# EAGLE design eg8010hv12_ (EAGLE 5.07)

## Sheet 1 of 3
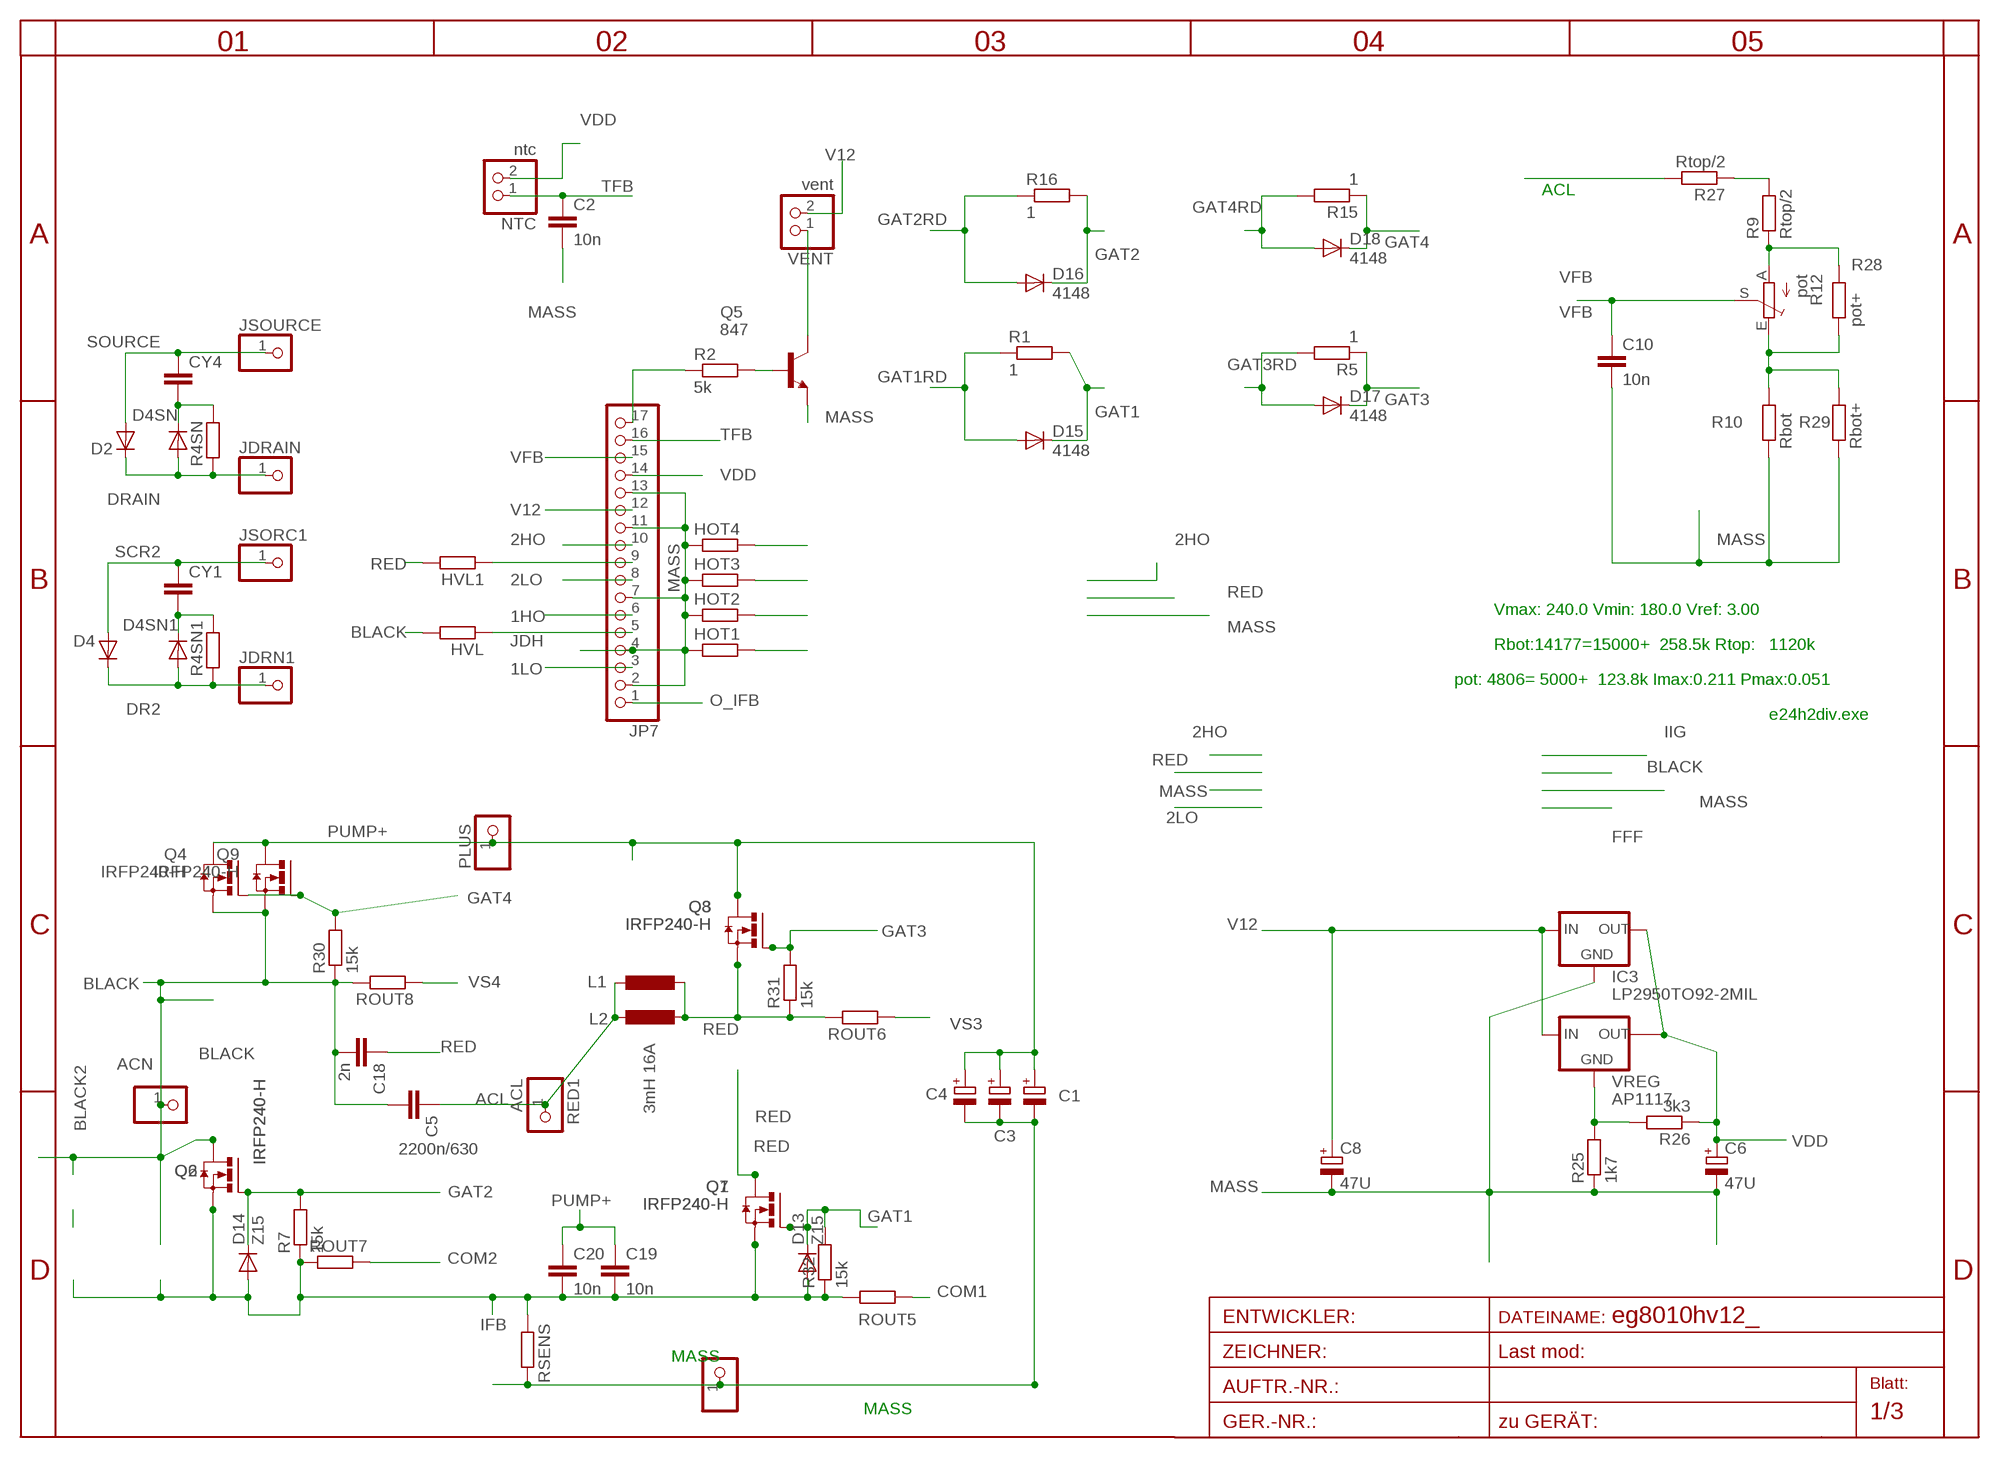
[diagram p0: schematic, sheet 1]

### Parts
BLACK2  ACN  PINHD-1X12MM3  [1X2MM3]
C1  CPOL-EUE5-13  [E5-13]
C2  10n  C-EUC0805  [C0805]
C3  CPOL-EUE5-13  [E5-13]
C4  CPOL-EUE5-13  [E5-13]
C5  2200n/630  C-EU275-173X316  [C275-173X316]
C6  47U  CPOL-EUSMCA  [SMC_A]
C8  47U  CPOL-EUSMCA  [SMC_A]
C10  10n  C-EUC0805  [C0805]
C18  2n  C-EU050-024X044  [C050-024X044]
C19  10n  C-EU050-024X044  [C050-024X044]
C20  10n  C-EU050-024X044  [C050-024X044]
CY1  CXXC10B5  [XC10B5]
CY4  CXXC10B5  [XC10B5]
D2  DIODE-SMC  [SMC]
D4  DIODE-SMC  [SMC]
D4SN  DIODE-P1-10  [P1-10]
D4SN1  DIODE-P1-10  [P1-10]
D13  Z15  DIODE-MINIMELF  [MINIMELF]
D14  Z15  DIODE-MINIMELF  [MINIMELF]
D15  4148  DIODE-MINIMELF  [MINIMELF]
D16  4148  DIODE-MINIMELF  [MINIMELF]
D17  4148  DIODE-MINIMELF  [MINIMELF]
D18  4148  DIODE-MINIMELF  [MINIMELF]
HOT1  R-EU_R0805  [R0805]
HOT2  R-EU_R0805  [R0805]
HOT3  R-EU_R0805  [R0805]
HOT4  R-EU_R0805  [R0805]
HVL  R-EU_R1005  [R1005]
HVL1  R-EU_R1005  [R1005]
IC3  LP2950TO92-2MIL  [TO92-2MIL]
JDRAIN  PINHD-1X11MM0  [1X1MM0]
JDRN1  PINHD-1X11MM0  [1X1MM0]
JP7  PINHD-1X17  [1X17]
JSORC1  PINHD-1X11MM0  [1X1MM0]
JSOURCE  PINHD-1X11MM0  [1X1MM0]
L1  L-EU4.13  [0204/13]
L2  3mH 16A  L-EURNG  [RING]
MINUS  PINHD-1X12MM3  [1X2MM3]
NTC  ntc  PINHD-1X2STR  [1X02]
PLUS  PINHD-1X12MM3  [1X2MM3]
Q1  IRFP240-H  [TO247BH]
Q2  IRFP240-H  [TO247BH]
Q3  IRFP240-H  [TO247BH]
Q4  IRFP240-H  [TO247BH]
Q5  847  BC847SMD  [SOT23]
Q6  IRFP240-H  [TO247BH]
Q7  IRFP240-H  [TO247BH]
Q8  IRFP240-H  [TO247BH]
Q9  IRFP240-H  [TO247BH]
R1  1  R-EU_R2512  [R2512]
R2  5k  R-EU_R0805  [R0805]
R4SN  R-EU_0207/10  [0207/10]
R4SN1  R-EU_0207/10  [0207/10]
R5  1  R-EU_R2512  [R2512]
R7  15k  R-EU_R1206  [R1206]
R9  Rtop/2  R-EU_R1206  [R1206]
R10  Rbot  R-EU_R0805  [R0805]
R12  pot  TRIM_EU-B64Y  [B64Y]
R15  1  R-EU_R2512  [R2512]
R16  1  R-EU_R2512  [R2512]
R25  1k7  R-EU_R0805  [R0805]
R26  3k3  R-EU_R0805  [R0805]
R27  Rtop/2  R-EU_R1206  [R1206]
R28  pot+  R-EU_R0805  [R0805]
R29  Rbot+  R-EU_R0805  [R0805]
R30  15k  R-EU_R1206  [R1206]
R31  15k  R-EU_R1206  [R1206]
R32  15k  R-EU_R1206  [R1206]
RED1  ACL  PINHD-1X12MM3  [1X2MM3]
ROUT5  R-EU_R2512  [R2512]
ROUT6  R-EU_R2512  [R2512]
ROUT7  R-EU_R2512  [R2512]
ROUT8  R-EU_R2512  [R2512]
RSENS  R-EU_WIRE  [WIRE]
VENT  vent  PINHD-1X2STR  [1X02]
VREG  AP1117  [SOT223]

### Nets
1HO: HOT2.2 JP7.6 ; also sheet 3
1LO: HOT1.2 JP7.3 ; also sheet 3
2HO: HOT4.2 JP7.10 ; also sheet 3
2LO: HOT3.2 JP7.8 ; also sheet 3
ACL: C5.1 L1.1 L2.2 R27.2 RED1.1
BLACK: BLACK2.1 C5.2 C18.2 HVL.2 Q2.D Q4.S Q6.D Q9.S R30.1 ROUT8.2
COM1: ROUT5.1 ; also sheet 3
COM2: ROUT7.2 ; also sheet 3
DFG: HVL1.1 JP7.9
DR2: D4.C D4SN1.A JDRN1.1 R4SN1.1
DRAIN: D2.C D4SN.A JDRAIN.1 R4SN.1
GAT1: D13.C D15.C Q1.G Q7.G R1.2 R32.2
GAT1RD: D15.A R1.1 ; also sheet 3
GAT2: D14.C D16.C Q2.G Q6.G R7.2 R16.2
GAT2RD: D16.A R16.1 ; also sheet 3
GAT3: D17.C Q3.G Q8.G R5.1 R31.2
GAT3RD: D17.A R5.2 ; also sheet 3
GAT4: D18.C Q4.G Q9.G R15.1 R30.2
GAT4RD: D18.A R15.2 ; also sheet 3
IFB: C19.2 C20.2 D13.A D14.A Q1.S Q2.S Q6.S Q7.S R7.1 R32.1 ROUT5.2 ROUT7.1 RSENS.1 ; also sheet 2,3
JDH: HVL.1 JP7.5
MASS: C1.- C2.2 C3.- C4.- C6.- C8.- C10.2 HOT1.1 HOT2.1 HOT3.1 HOT4.1 IC3.2(GND) JP7.2 JP7.4 JP7.7 JP7.11 JP7.13 MINUS.1 Q5.2(E) R10.1 R25.1 R29.1 RSENS.2 ; also sheet 2,3
N$1: Q5.3(C) VENT.1
N$2: Q5.1(B) R2.2
N$3: JP7.17 R2.1
N$17: R25.2 R26.2 VREG.1(GND)
N$23: R9.2 R27.1
N$29: R10.2 R12.E R28.1 R29.2
N$30: R9.1 R12.A R28.2
O_IFB: JP7.1 ; also sheet 3
PUMP+: C1.+ C3.+ C4.+ C19.1 C20.1 PLUS.1 Q3.D Q4.D Q8.D Q9.D ; also sheet 2
RED: C18.1 HVL1.2 L1.2 L2.1 Q1.D Q3.S Q7.D Q8.S R31.1 ROUT6.2
SCR2: CY1.1 D4.A JSORC1.1
SNUB1: CY1.2 D4SN1.C R4SN1.2
SNUB2: CY4.2 D4SN.C R4SN.2
SOURCE: CY4.1 D2.A JSOURCE.1
TFB: C2.1 JP7.16 NTC.1 ; also sheet 2
V12: C8.+ IC3.3(IN) JP7.12 VENT.2 VREG.3(IN) ; also sheet 2,3
VDD: C6.+ IC3.1(OUT) JP7.14 NTC.2 R26.1 VREG.4(TAB) ; also sheet 2,3
VFB: C10.1 JP7.15 R12.S ; also sheet 2
VS3: ROUT6.1 ; also sheet 3
VS4: ROUT8.1 ; also sheet 3
Unconnected: VREG.2(OUT)

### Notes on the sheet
- Vmax: 240.0 Vmin: 180.0 Vref: 3.00
- Rbot:14177=15000+  258.5k Rtop:   1120k
- pot: 4806= 5000+  123.8k Imax:0.211 Pmax:0.051
- e24h2div.exe

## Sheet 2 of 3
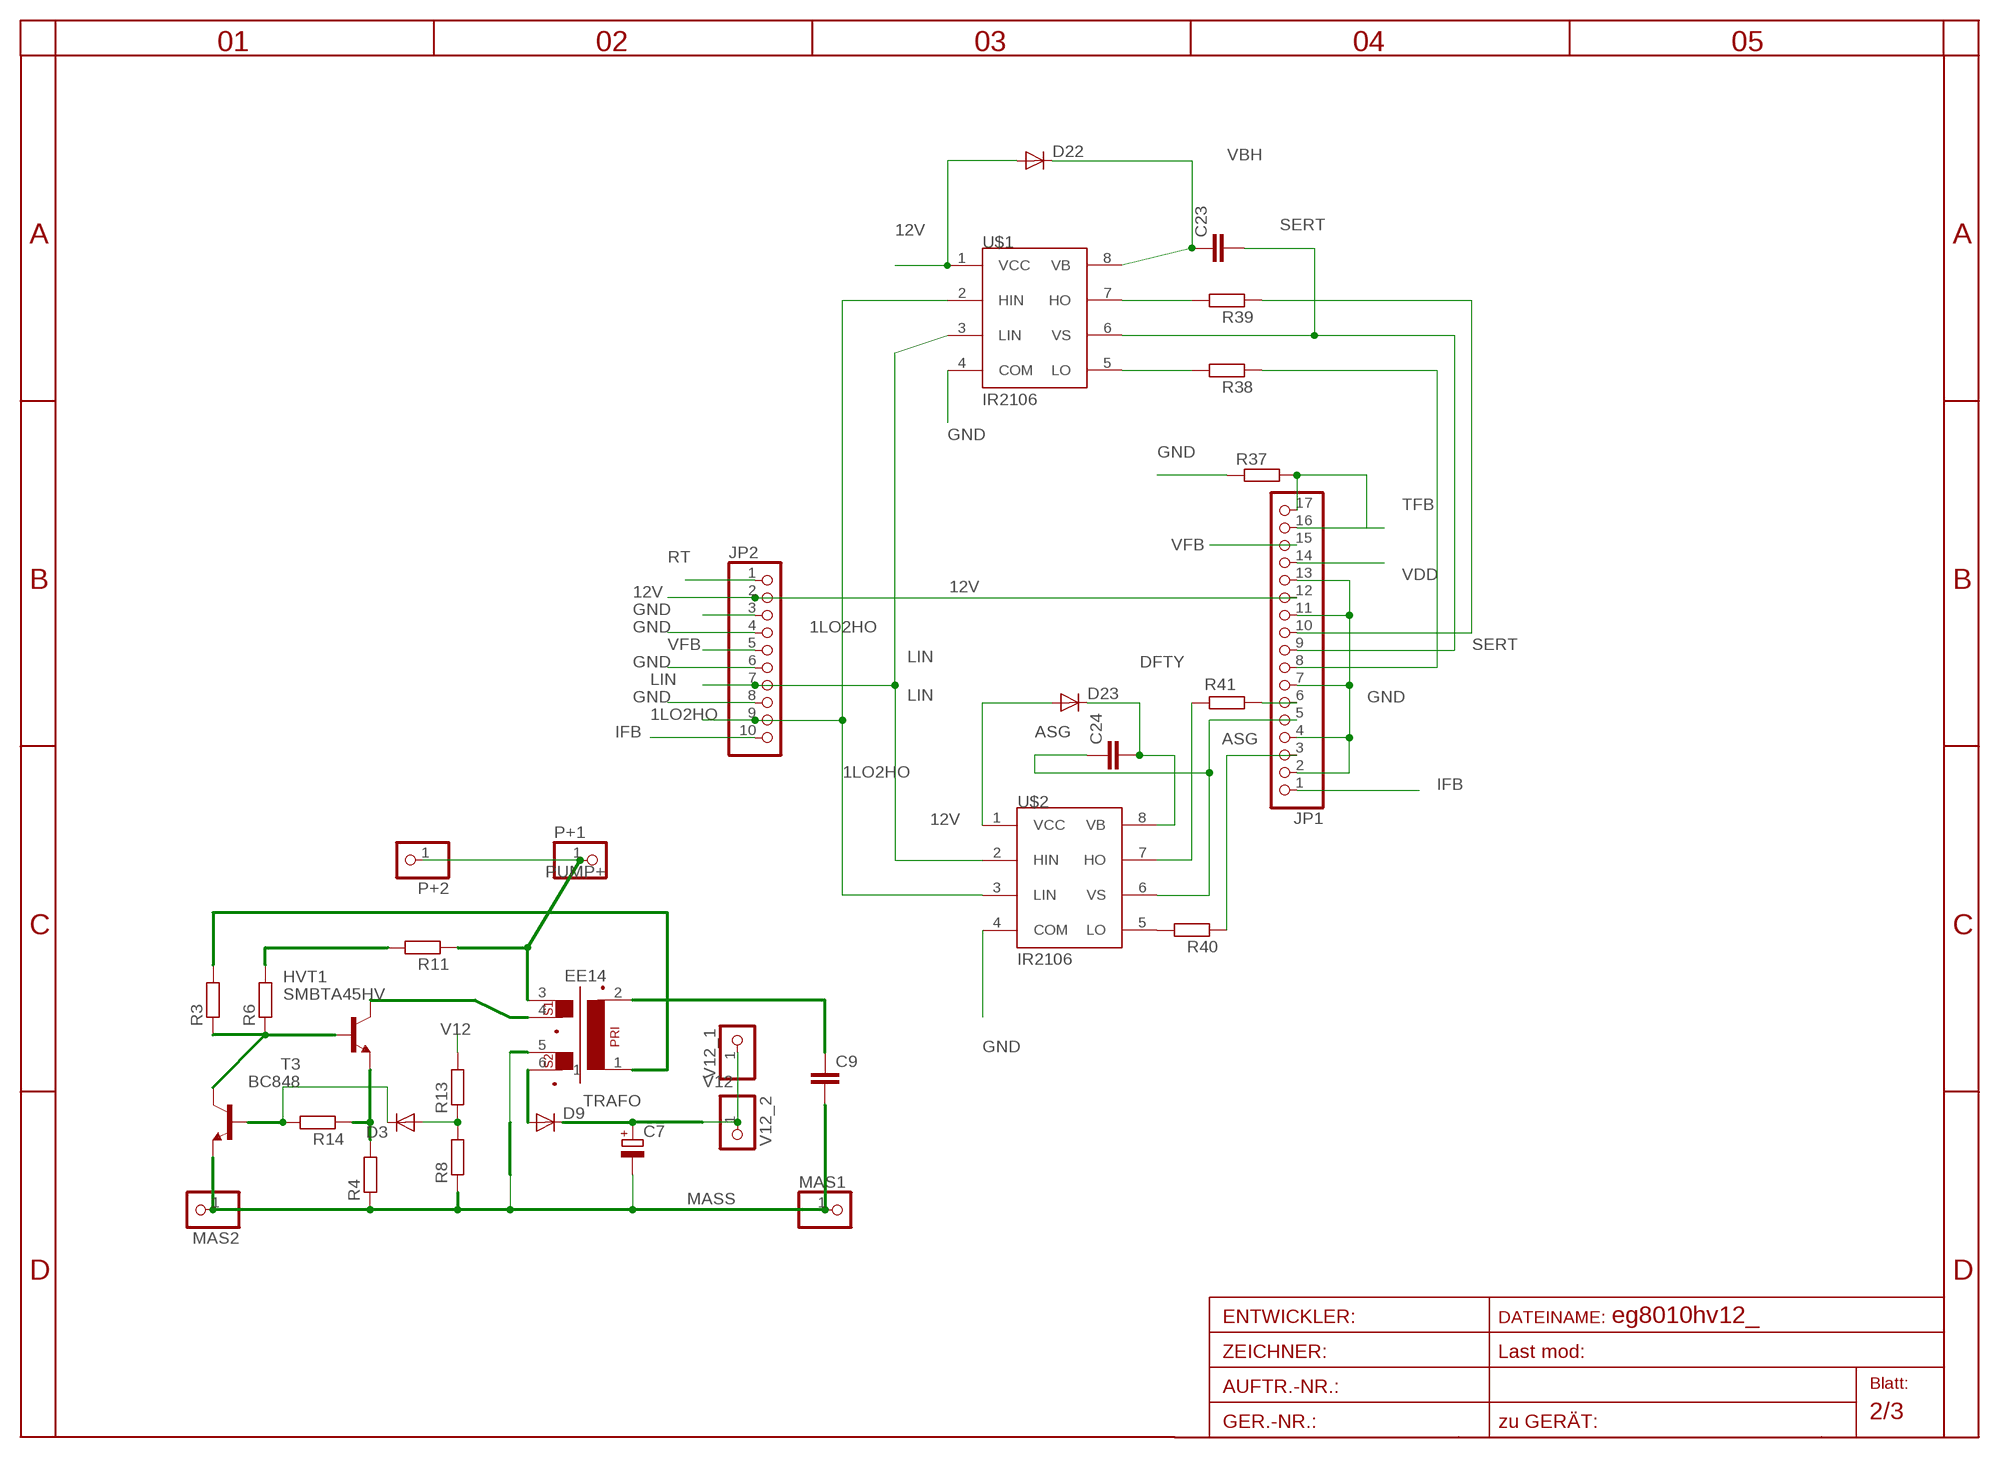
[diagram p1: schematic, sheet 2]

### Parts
C7  CPOL-EUSMCA  [SMC_A]
C9  C-EUC0805  [C0805]
C23  C-EUC1206  [C1206]
C24  C-EUC1206  [C1206]
D3  DIODE-MINIMELF  [MINIMELF]
D9  DIODE-SMA-DO214  [SMA-DO214AC]
D22  DIODE-SMA-DO214  [SMA-DO214AC]
D23  DIODE-SMA-DO214  [SMA-DO214AC]
HVT1  SMBTA45HV  [SOT23HV]
JP1  PINHD-1X17  [1X17]
JP2  PINHD-1X100X05  [1X10]
MAS1  PINHD-1X11X0.4  [1X01]
MAS2  PINHD-1X11X0.4  [1X01]
P+1  PINHD-1X11X0.4  [1X01]
P+2  PINHD-1X11X0.4  [1X01]
R3  R-EU_R0805  [R0805]
R4  R-EU_R0805  [R0805]
R6  R-EU_R1206  [R1206]
R8  R-EU_R0805  [R0805]
R11  R-EU_R1206  [R1206]
R13  R-EU_R0805  [R0805]
R14  R-EU_R0805  [R0805]
R37  R-EU_0204/2V  [0204V]
R38  R-EU_R1206  [R1206]
R39  R-EU_R1206  [R1206]
R40  R-EU_R1206  [R1206]
R41  R-EU_R1206  [R1206]
T3  BC848  [SOT23]
TRAFO  EE14  [EE14]
U$1  IR2106  [SO8-5]
U$2  IR2106  [SO8-5]
V12_1  PINHD-1X11X0.4  [1X01]
V12_2  PINHD-1X11X0.4  [1X01]

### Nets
1LO2HO: JP2.9 U$1.2(HIN) U$2.3(LIN)
12V: D22.A D23.A JP1.12 JP2.2 U$1.1(VCC) U$2.1(VCC)
A: D9.A TRAFO.6
ASG: C24.1 JP1.5 U$2.6(VS)
B1C2: HVT1.1(B) R3.1 R6.1 T3.C
BT1: D3.C R14.2 T3.B
C1: HVT1.3(C) TRAFO.4
DFTY: C24.2 D23.K(C) U$2.8(VB)
EB: HVT1.2(E) R4.2 R14.1
GND: JP1.2 JP1.4 JP1.7 JP1.11 JP1.13 JP2.3 JP2.4 JP2.6 JP2.8 R37.1 U$1.4(COM) U$2.4(COM)
IFB: JP1.1 JP2.10 ; also sheet 1,3
LIN: JP2.7 U$1.3(LIN) U$2.2(HIN)
MASS: C7.- C9.2 MAS1.1 MAS2.1 R4.1 R8.1 T3.E TRAFO.5 ; also sheet 1,3
N$6: R3.2 TRAFO.1
N$7: C9.1 TRAFO.2
N$8: R6.2 R11.2
N$10: D3.A R8.2 R13.1
N$15: JP1.3 R40.1
N$19: R41.2 U$2.7(HO)
N$21: JP1.8 R38.1
N$27: JP1.10 R39.1
N$32: R38.2 U$1.5(LO)
N$33: R39.2 U$1.7(HO)
N$34: JP1.6 R41.1
N$35: R40.2 U$2.5(LO)
PUMP+: P+1.1 P+2.1 R11.1 TRAFO.3 ; also sheet 1
RT: JP2.1
SERT: C23.2 JP1.9 U$1.6(VS)
TFB: JP1.16 JP1.17 R37.2 ; also sheet 1
V12: C7.+ D9.K(C) R13.2 V12_1.1 V12_2.1 ; also sheet 1,3
VBH: C23.1 D22.K(C) U$1.8(VB)
VDD: JP1.14 ; also sheet 1,3
VFB: JP1.15 JP2.5 ; also sheet 1

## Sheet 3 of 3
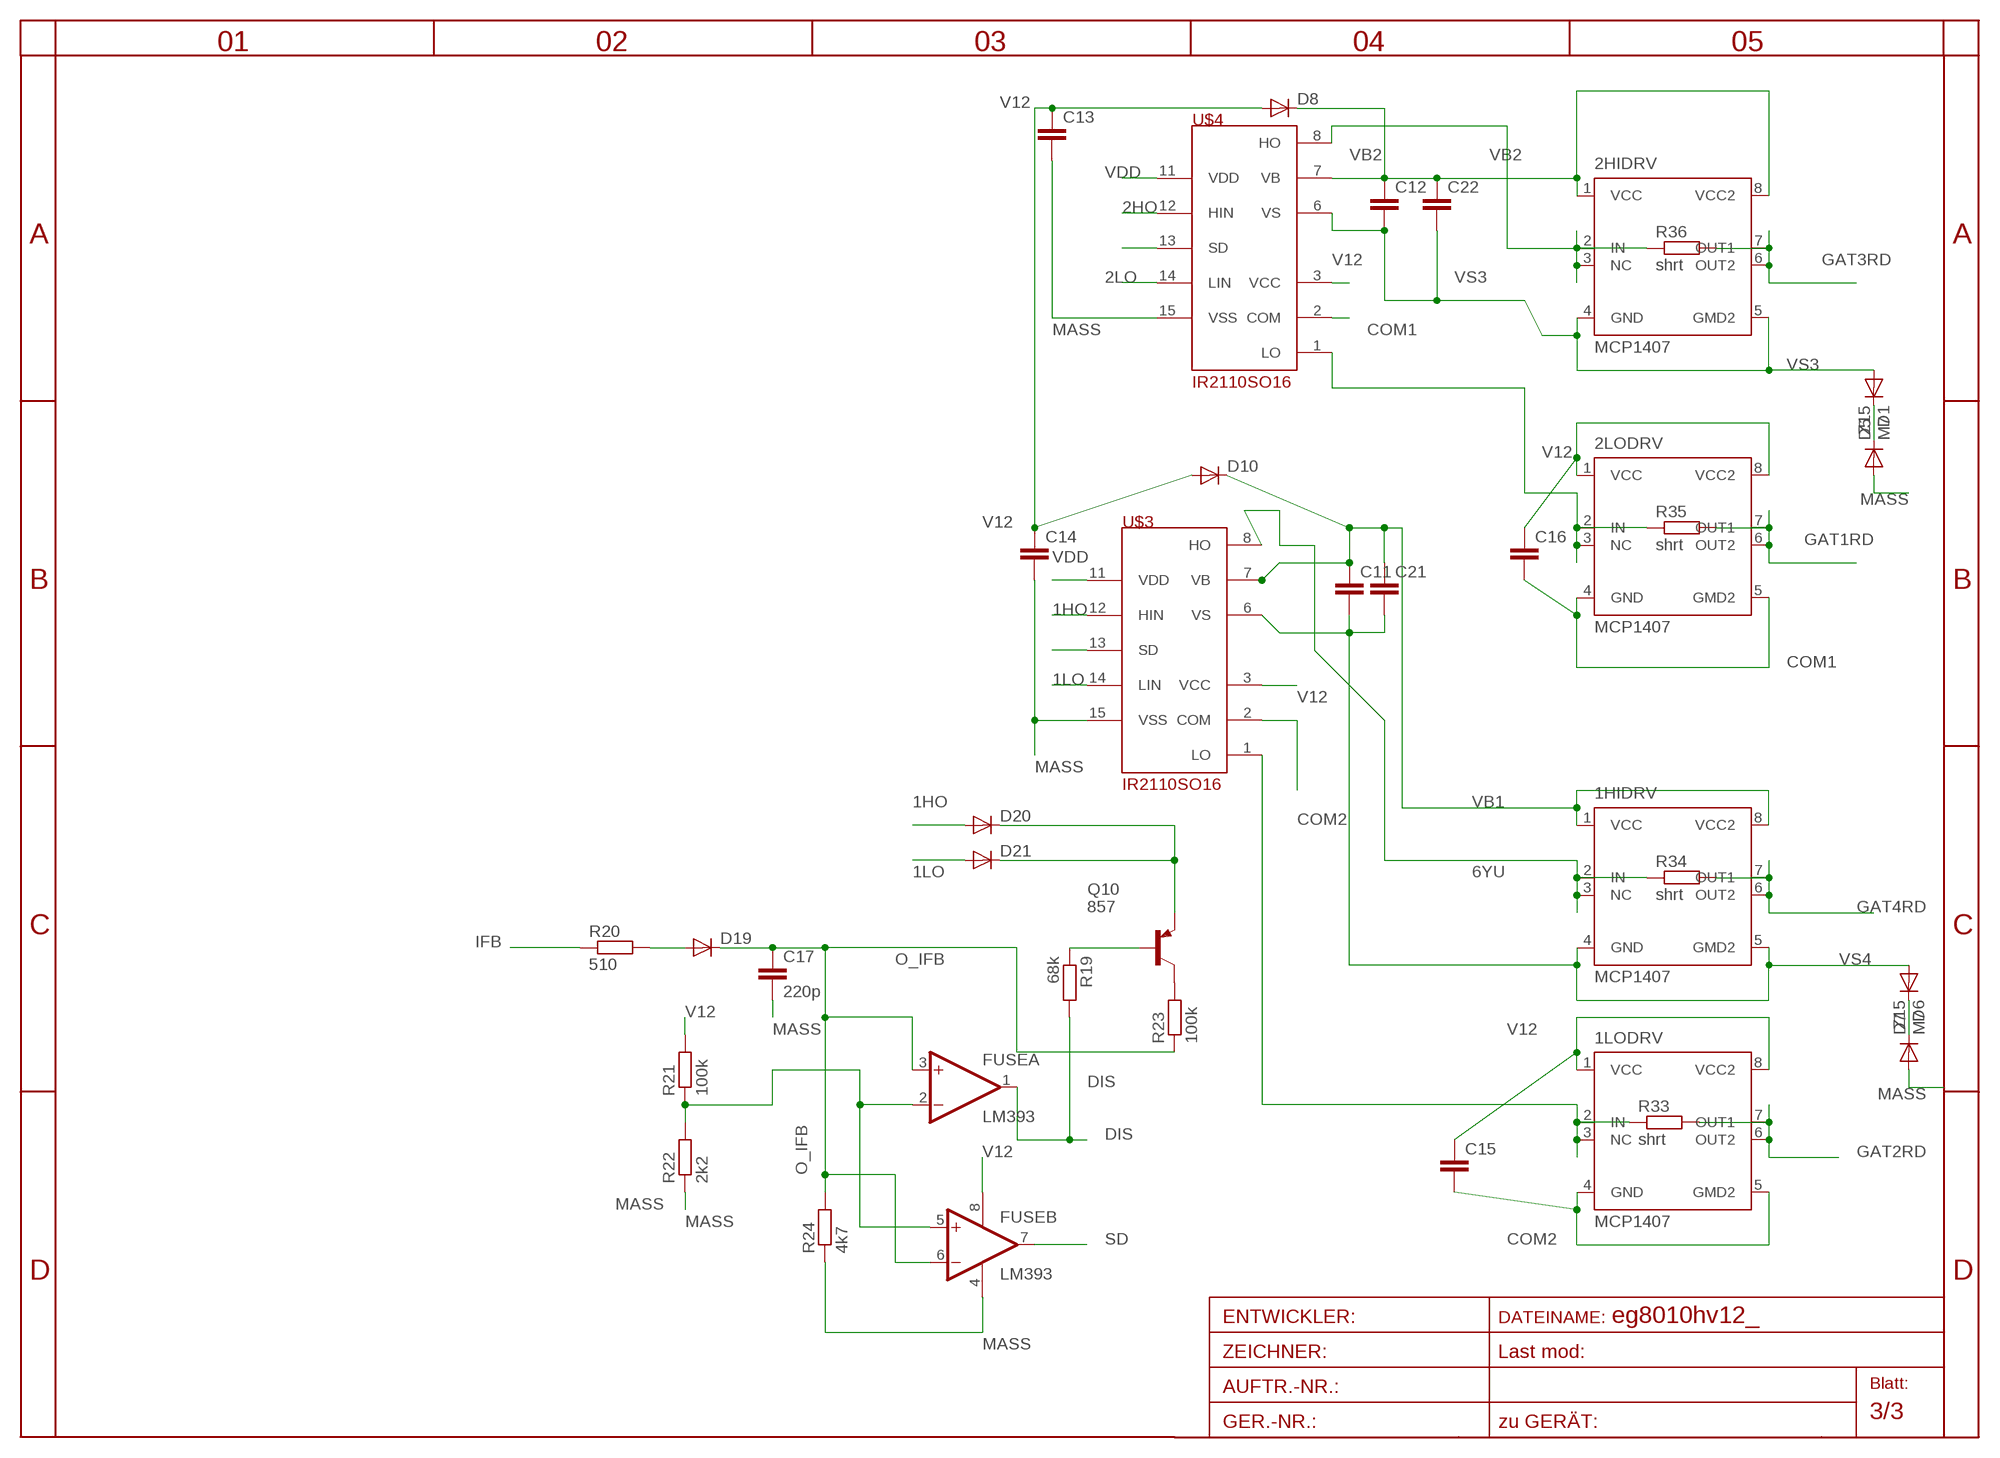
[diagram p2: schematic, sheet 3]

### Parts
1HIDRV  MCP1407  [SO-08M]
1LODRV  MCP1407  [SO-08M]
2HIDRV  MCP1407  [SO-08M]
2LODRV  MCP1407  [SO-08M]
C11  C-EUC058MLCC  [C058-020X040]
C12  C-EUC058MLCC  [C058-020X040]
C13  C-EUC1206  [C1206]
C14  C-EUC1206  [C1206]
C15  C-EUC1206  [C1206]
C16  C-EUC1206  [C1206]
C17  220p  C-EUC0805  [C0805]
C21  C-EUC1206  [C1206]
C22  C-EUC1206  [C1206]
D1  Z15  DIODE-MINIMELF  [MINIMELF]
D5  M7  DIODE-SMA-DO214  [SMA-DO214AC]
D6  Z15  DIODE-MINIMELF  [MINIMELF]
D7  M7  DIODE-SMA-DO214  [SMA-DO214AC]
D8  DIODE-SMA-DO214  [SMA-DO214AC]
D10  DIODE-SMA-DO214  [SMA-DO214AC]
D19  DIODE-SOT23  [SOT23]
D20  DIODE-SOT23  [SOT23]
D21  DIODE-SOT23  [SOT23]
FUSE  LM393  LM358D  [SO08]
Q10  857  BC857ALT1SMD  [SOT23-BEC]
R19  68k  R-EU_R0805  [R0805]
R20  510  R-EU_R0805  [R0805]
R21  100k  R-EU_R0805  [R0805]
R22  2k2  R-EU_R0805  [R0805]
R23  100k  R-EU_R0805  [R0805]
R24  4k7  R-EU_R0805  [R0805]
R33  shrt  R-EU_R1206  [R1206]
R34  shrt  R-EU_R1206  [R1206]
R35  shrt  R-EU_R1206  [R1206]
R36  shrt  R-EU_R1206  [R1206]
U$3  IR2110SO16  [SO16DW]
U$4  IR2110SO16  [SO16DW]

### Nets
1HO: D20.1(A) U$3.12(HIN) ; also sheet 1
1LO: D21.1(A) U$3.14(LIN) ; also sheet 1
2HO: U$4.12(HIN) ; also sheet 1
2LO: U$4.14(LIN) ; also sheet 1
6YU: 1HIDRV.2(IN) 1HIDRV.3(NC) R34.1 U$3.8(HO)
COM1: 2LODRV.4(GND) 2LODRV.5(GMD2) C16.2 U$4.2(COM) ; also sheet 1
COM2: 1LODRV.4(GND) 1LODRV.5(GMD2) C15.2 U$3.2(COM) ; also sheet 1
DIS: FUSE.1(A:OUT) R19.2
ET: 1LODRV.2(IN) 1LODRV.3(NC) R33.1 U$3.1(LO)
GAT1RD: 2LODRV.6(OUT2) 2LODRV.7(OUT1) R35.2 ; also sheet 1
GAT2RD: 1LODRV.6(OUT2) 1LODRV.7(OUT1) R33.2 ; also sheet 1
GAT3RD: 2HIDRV.6(OUT2) 2HIDRV.7(OUT1) R36.2 ; also sheet 1
GAT4RD: 1HIDRV.6(OUT2) 1HIDRV.7(OUT1) R34.2 ; also sheet 1
IFB: R20.1 ; also sheet 1,2
MASS: C13.2 C14.2 C17.2 D5.A D7.A FUSE.4(P:V-) R22.1 R24.1 U$3.15(VSS) U$4.15(VSS) ; also sheet 1,2
N$9: FUSE.2(A:-IN) FUSE.5(B:+IN) R21.1 R22.2
N$12: 2HIDRV.2(IN) 2HIDRV.3(NC) R36.1 U$4.8(HO)
N$14: D19.1(A) R20.2
N$16: 2LODRV.2(IN) 2LODRV.3(NC) R35.1 U$4.1(LO)
N$18: D20.3(C) D21.3(C) Q10.E
N$20: D1.C D5.K(C)
N$24: D6.C D7.K(C)
N$25: Q10.B R19.1
N$26: Q10.C R23.2
O_IFB: C17.1 D19.3(C) FUSE.3(A:+IN) FUSE.6(B:-IN) R23.1 R24.2 ; also sheet 1
SD: FUSE.7(B:OUT) U$3.13(SD) U$4.13(SD)
V12: 1LODRV.1(VCC) 1LODRV.8(VCC2) 2LODRV.1(VCC) 2LODRV.8(VCC2) C13.1 C14.1 C15.1 C16.1 D8.A D10.A FUSE.8(P:V+) R21.2 U$3.3(VCC) U$4.3(VCC) ; also sheet 1,2
VB1: 1HIDRV.1(VCC) 1HIDRV.8(VCC2) C11.1 C21.1 D10.K(C) U$3.7(VB)
VB2: 2HIDRV.1(VCC) 2HIDRV.8(VCC2) C12.1 C22.1 D8.K(C) U$4.7(VB)
VDD: U$3.11(VDD) U$4.11(VDD) ; also sheet 1,2
VS3: 2HIDRV.4(GND) 2HIDRV.5(GMD2) C12.2 C22.2 D1.A U$4.6(VS) ; also sheet 1
VS4: 1HIDRV.4(GND) 1HIDRV.5(GMD2) C11.2 C21.2 D6.A U$3.6(VS) ; also sheet 1

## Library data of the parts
1HIDRV 1LODRV 2HIDRV 2LODRV = microchip:MCP1407
BLACK2 JDRAIN JDRN1 JSORC1 JSOURCE MAS1 MAS2 MINUS P+1 P+2 PLUS RED1 V12_1 V12_2 = pinhead:PINHD-1X1: PIN HEADER
C1 C3 C4 C6-C8 = rcl:CPOL-EU: POLARIZED CAPACITOR, European symbol
C2 C5 C9-C24 = rcl:C-EU: CAPACITOR, European symbol
CY1 CY4 = rcl:CX: X CAPACITOR
D1-D4 D4SN D4SN1 D5-D10 D13-D23 = diode:DIODE-: DIODE
FUSE = linear:LM358: OP AMP also LM158; LM258; LM2904 Source: http://cache.national.com/ds/LM/LM158.pdf
HOT1-HOT4 HVL HVL1 R1-R4 R4SN R4SN1 R5-R8 R11 R13-R16 R19-R24 R30-R41 ROUT5-ROUT8 RSENS = rcl:R-EU_: RESISTOR, European symbol
HVT1 = transistor-npn:SMBTA45
IC3 = v-reg:LP2950?*: Source: http://cache.national.com/ds/LP/LP2950.pdf
JP1 JP7 = pinhead:PINHD-1X17: PIN HEADER
JP2 = pinhead:PINHD-1X10: PIN HEADER
L1 L2 = rcl:L-EU: INDUCTOR, European symbol
NTC VENT = pinhead:PINHD-1X2: PIN HEADER
Q1-Q4 Q6-Q9 = transistor-power:IRFP240: HEXFET Power MosFet Source: http://www.irf.com/
Q5 = transistor-npn:BC847*: NPN Transistor
Q10 = transistor-pnp:BC857*: PNP Transistror
R9 R10 R25-R29 = rcl-2:R-EU_: RESISTOR, European symbol
R12 = pot:TRIM_EU-: POTENTIOMETER
T3 = transistor:BC848: NPN TRANSISTOR
TRAFO = trafo:EE14
U$1 U$2 = irf-2:IR2106
U$3 U$4 = ir2112:IR2110
VREG = v-reg:AP1117

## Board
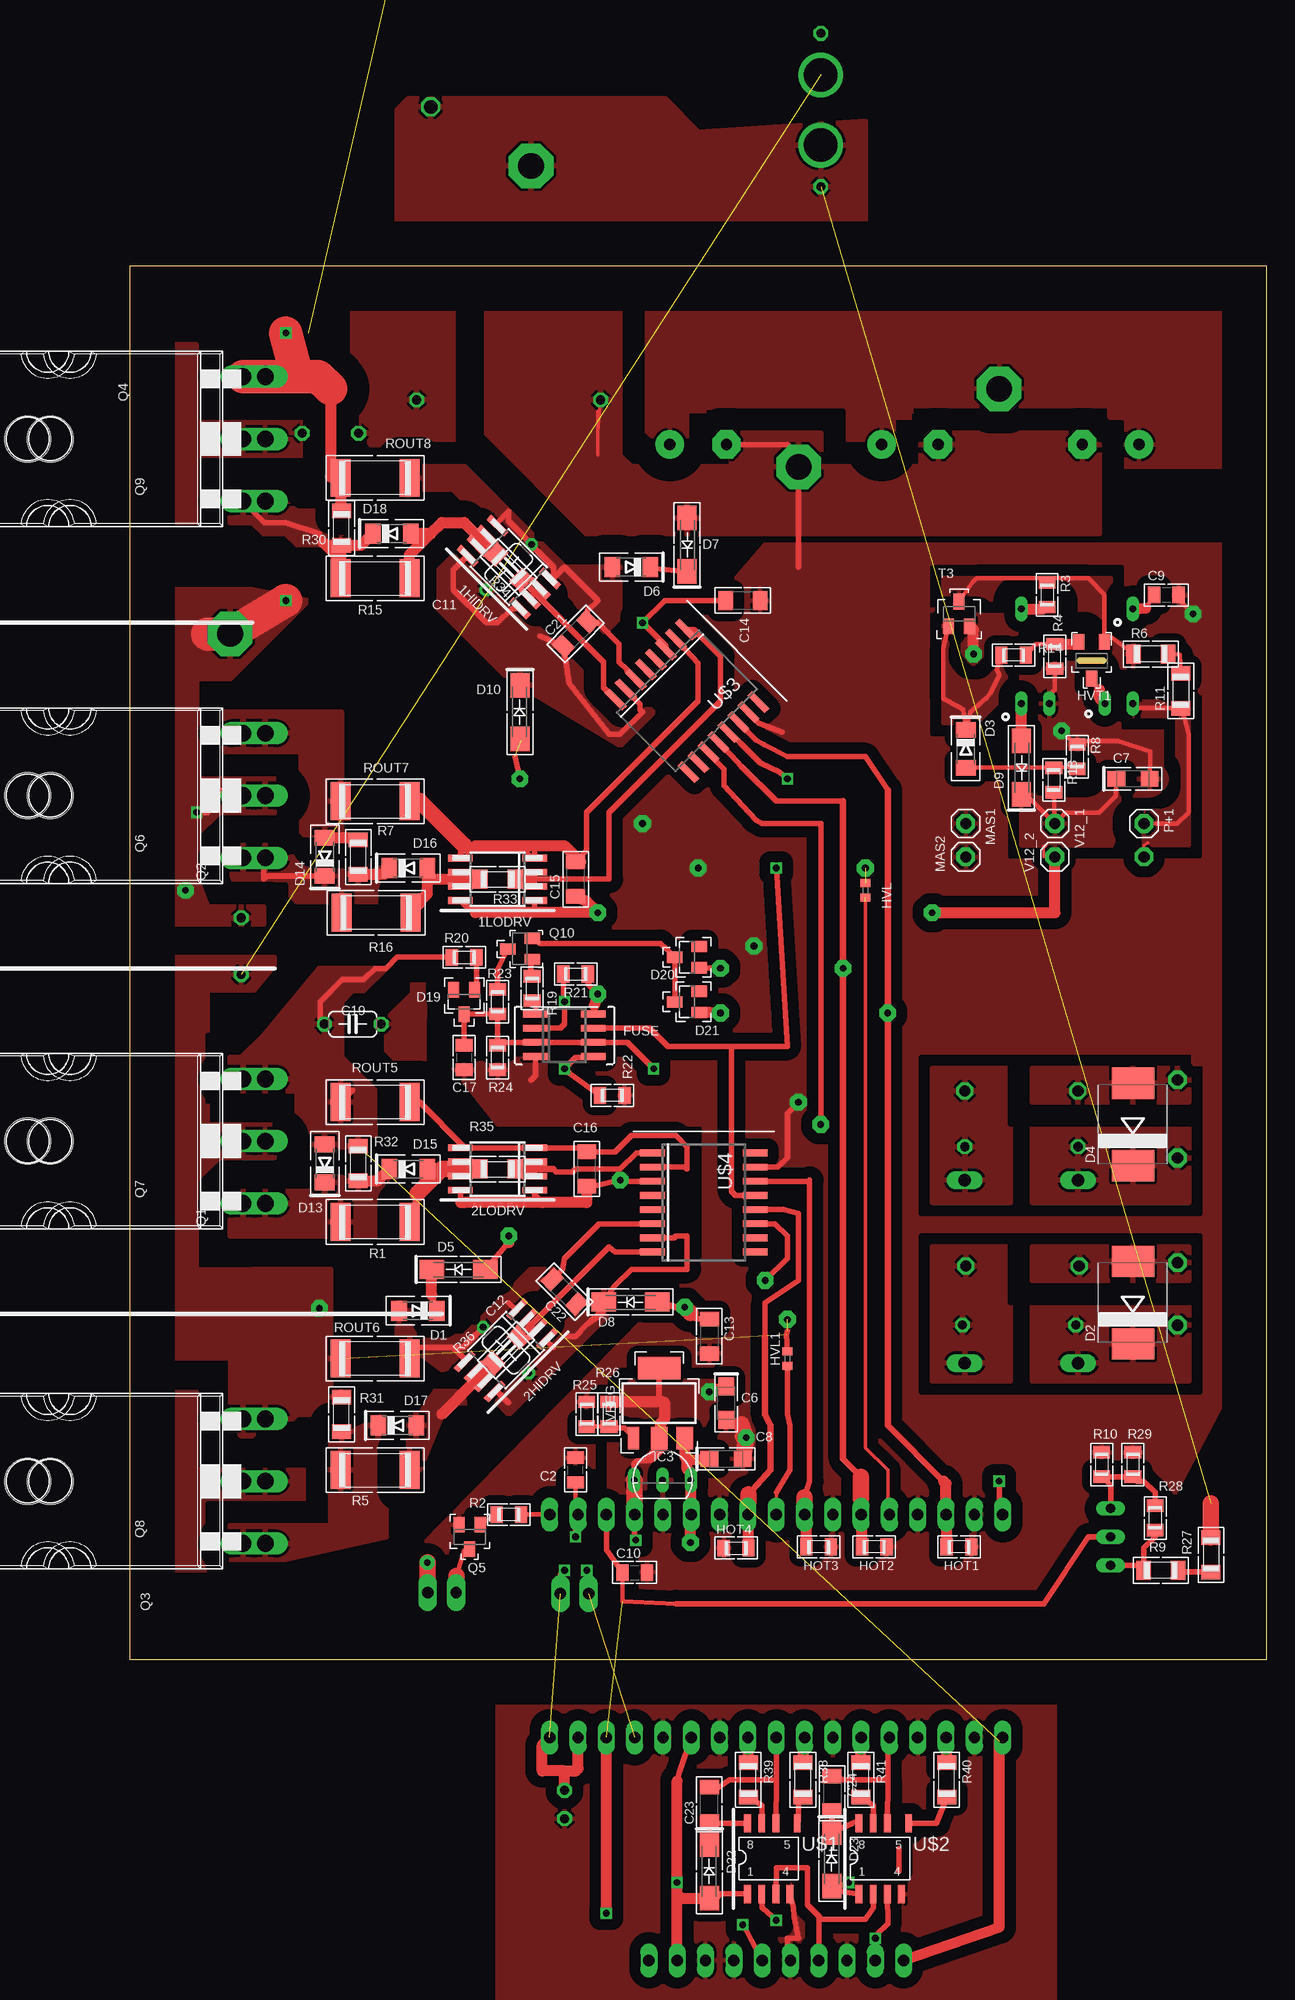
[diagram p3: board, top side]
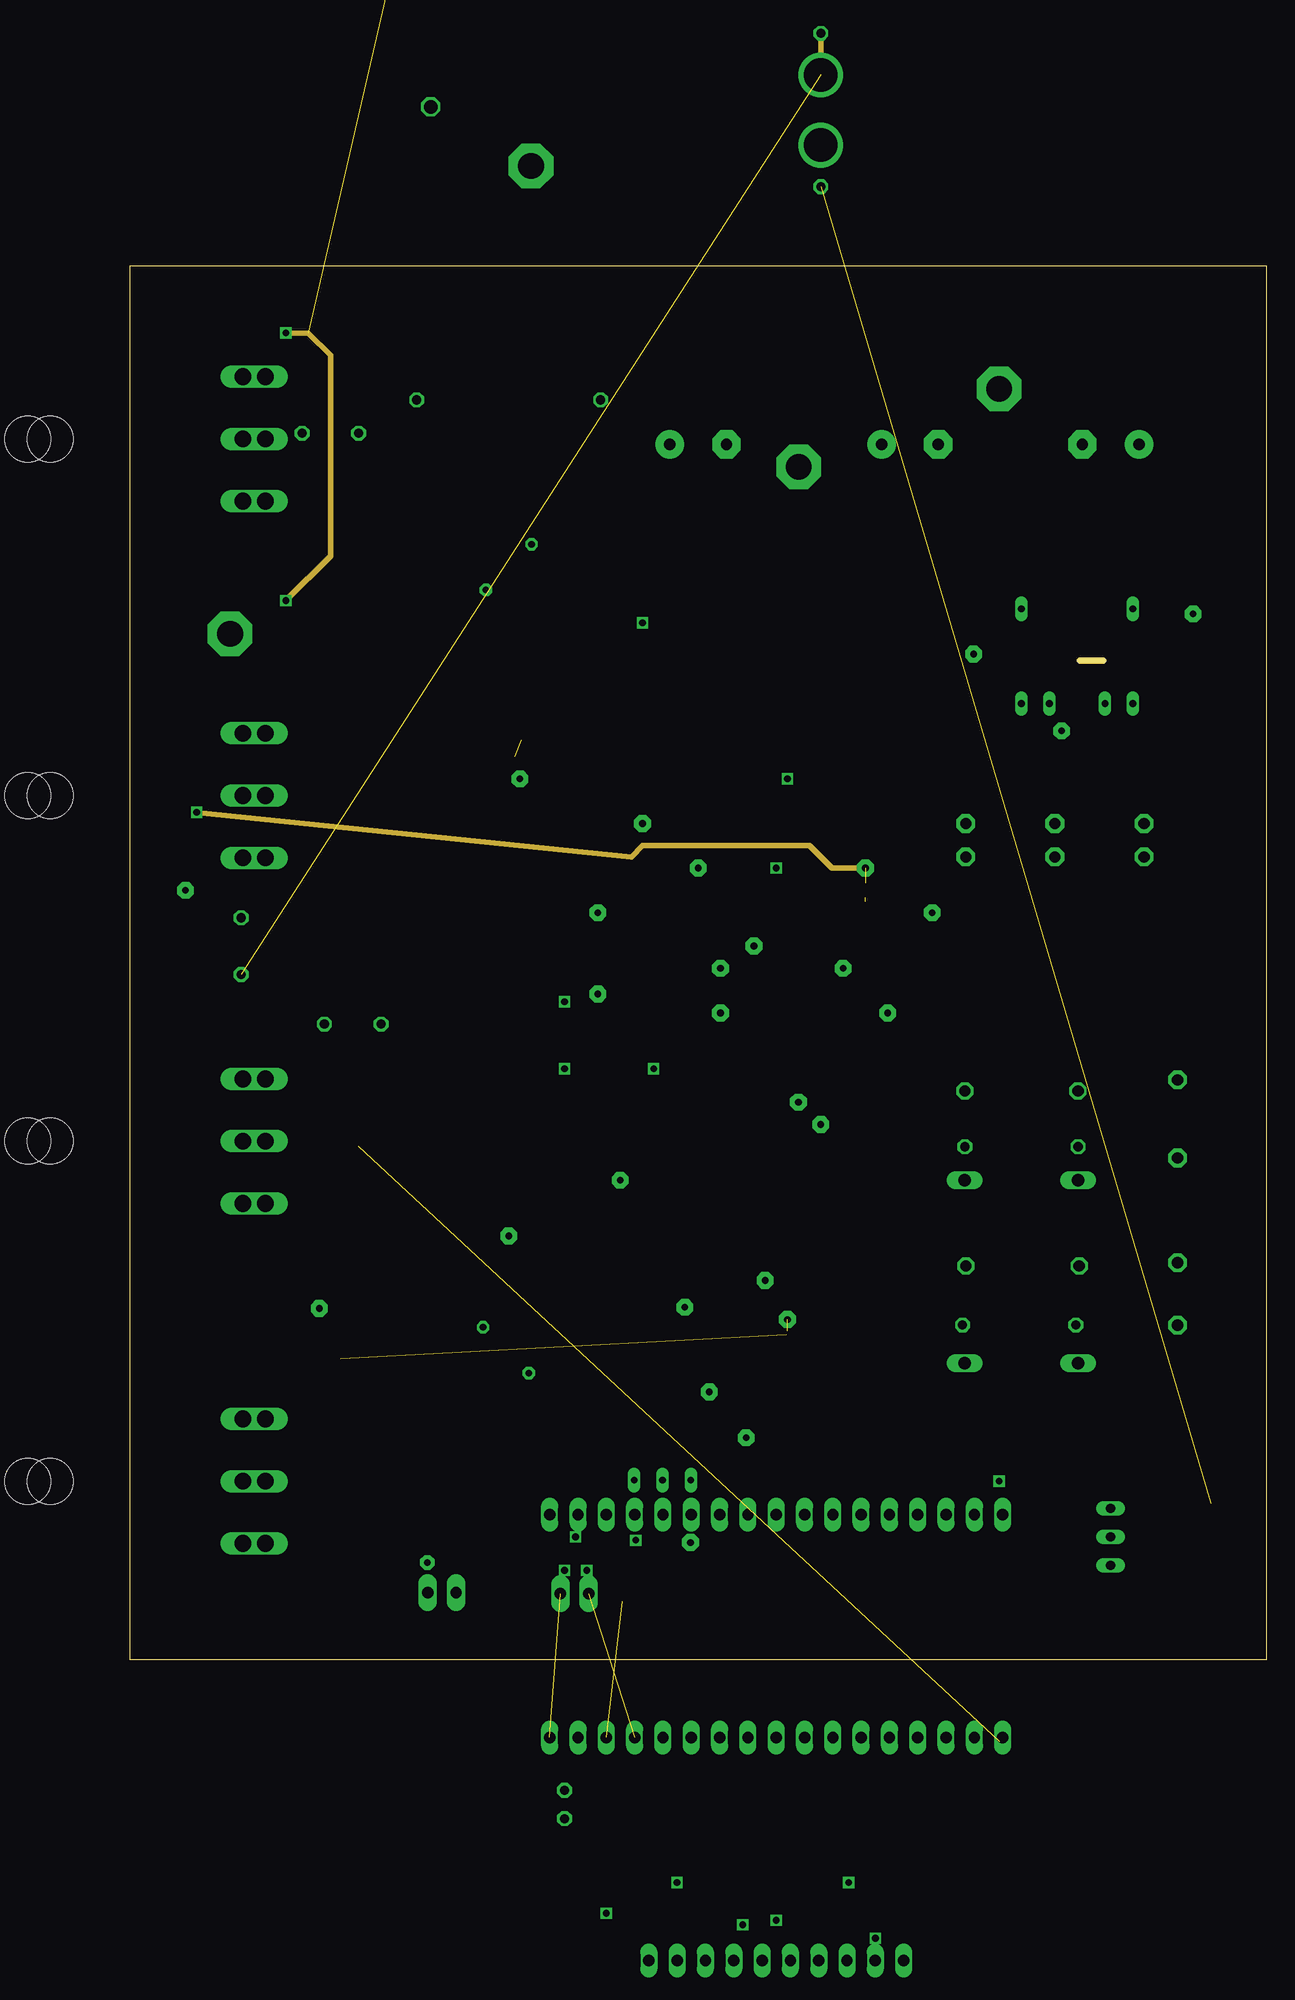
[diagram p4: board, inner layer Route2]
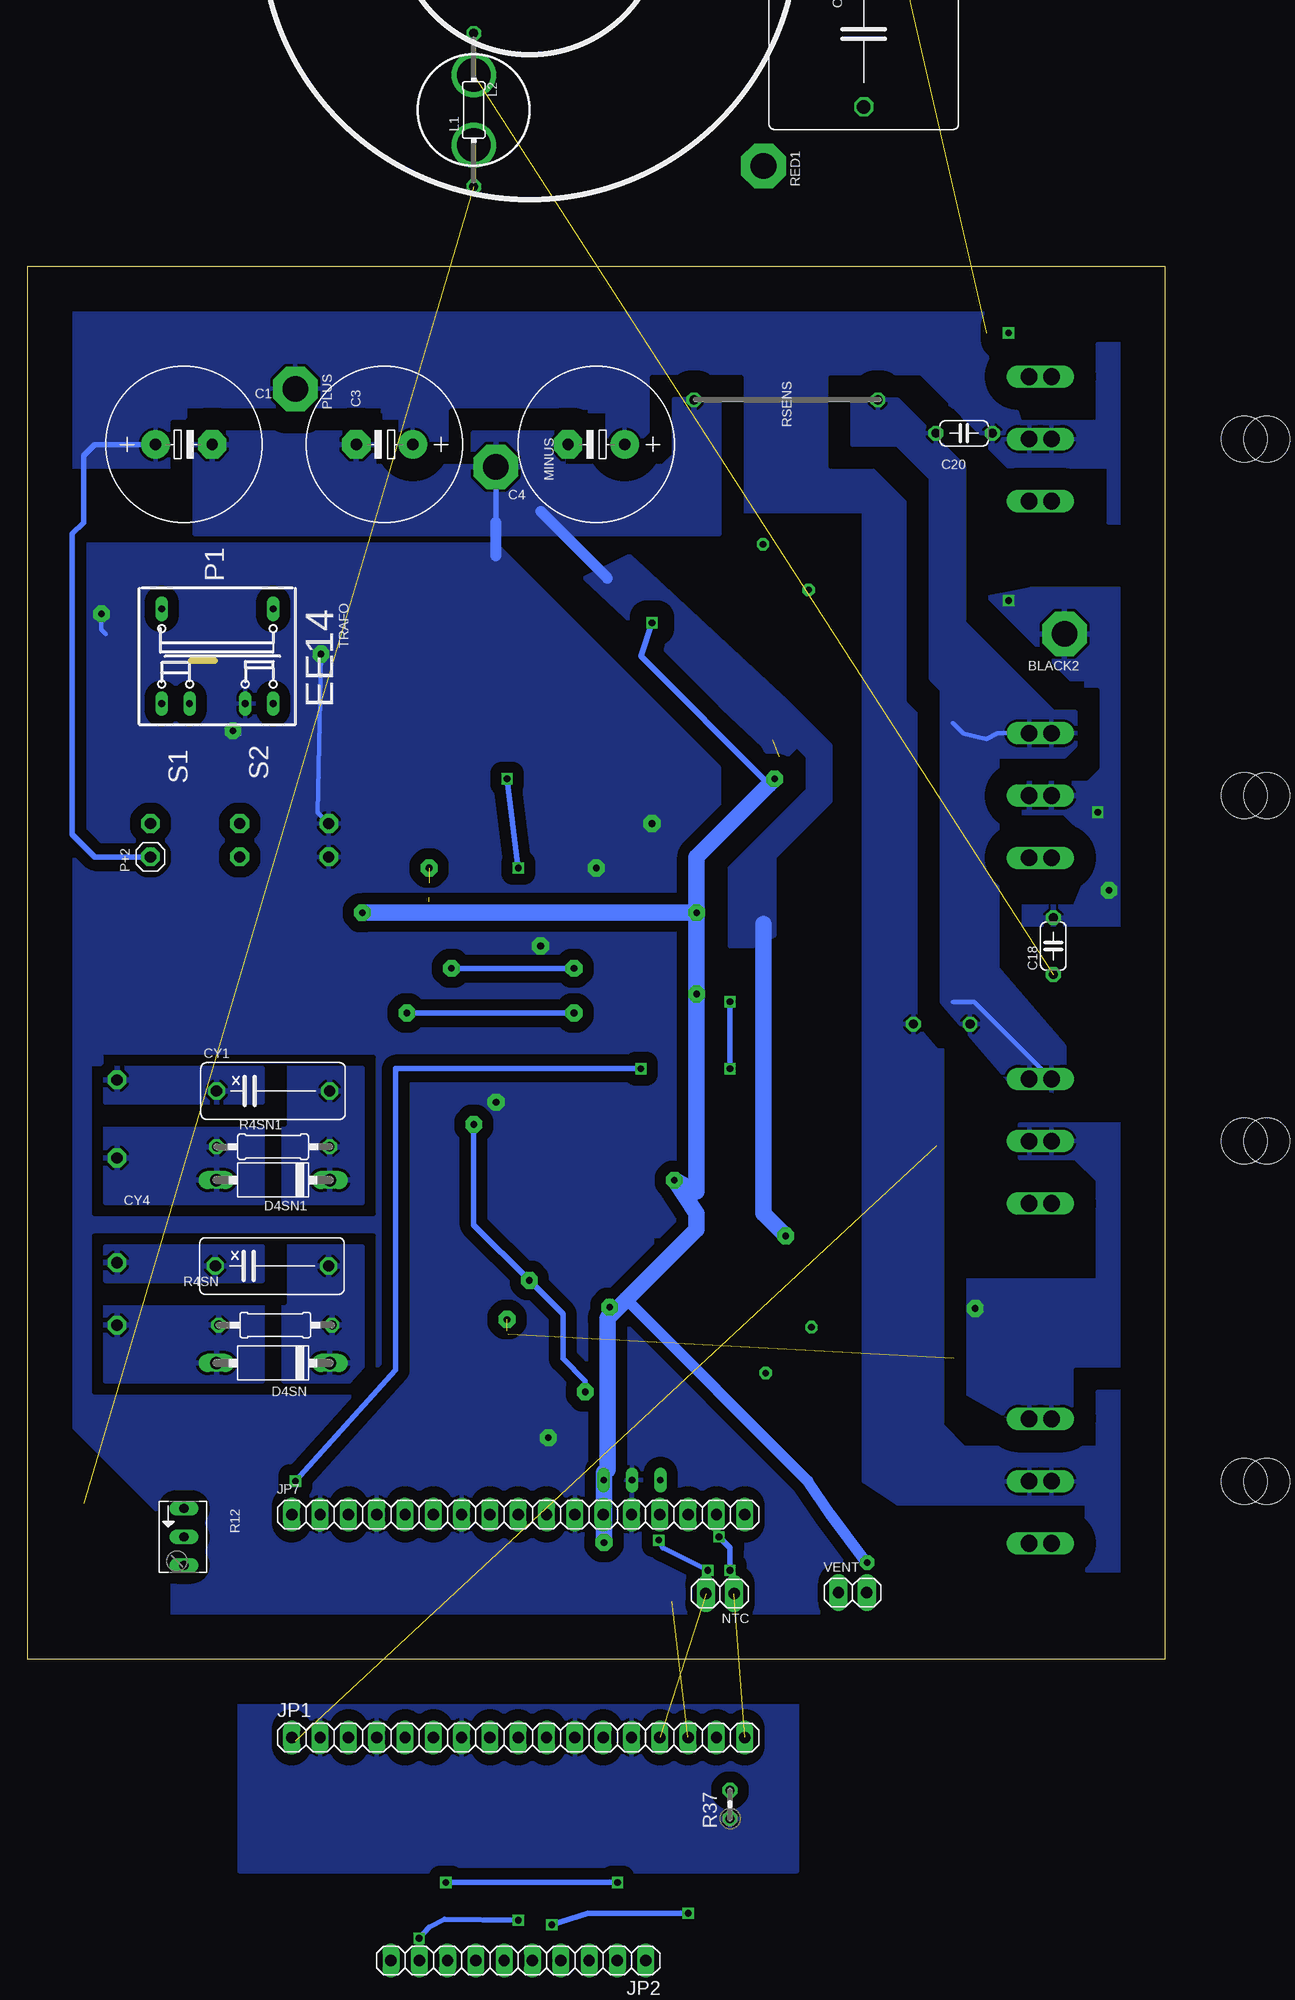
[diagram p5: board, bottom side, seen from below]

Size 102 x 125 mm. Coordinates in mm from the lower left corner, seen from the top.
Outline: 0,0 102,0 102,125 0,125 0,0
Copper layers (1*16): Top 0.035mm / dielectric 1.5mm / Bottom 0.035mm
Design rules "default *": minimum track width 10mil, minimum drill 20mil, track to track 8mil, track to pad 8mil, pad to pad 8mil, via to via 8mil, smd to smd 8mil, copper to edge 4mm, drill to drill 8mil, minimum pad ring 10mil, minimum via ring 8mil, stop-mask expansion 4mil, vias tented up to drill 0mil, thermal gap 10mil

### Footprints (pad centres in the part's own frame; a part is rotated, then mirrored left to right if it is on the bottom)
SO-08M = smd 0.6 x 2.2: 1 -1.905,-3.33; 2 -0.635,-3.33; 3 0.635,-3.33; 4 1.905,-3.33; 5 1.905,3.33; 6 0.635,3.33; 7 -0.635,3.33; 8 -1.905,3.33
1X2MM3 = drill 2.3 pad 4 octagon: 1 0,0
E5-13 = drill 1.016 pad 2.54 round: + -2.54,0 | drill 1.016 pad 2.54 octagon: - 2.54,0
C0805 = smd 1.1 x 1.5: 1 -1.1,0; 2 1.1,0
C275-173X316 = drill 1.194 octagon: 1 -13.716,0; 2 13.716,0
SMC_A = smd 1.6 x 1.4: + -1.5,0; - 1.5,0
C058-020X040 = drill 0.6 octagon: 1 -2.9,0; 2 2.9,0
C1206 = smd 1.3 x 1.7: 1 -1.55,0; 2 1.55,0
C050-024X044 = drill 0.813 octagon: 1 -2.54,0; 2 2.54,0
XC10B5 = drill 1.016 octagon: 1 -5.08,0; 2 5.08,0
MINIMELF = smd 1.4 x 1.8: A 1.7,0; C -1.7,0
SMC = smd 2.8 x 3.8: A 3.7,0; C -3.7,0
P1-10 = drill 1.118 long: A 5.08,0; C -5.08,0
SMA-DO214AC = smd 2.2 x 1.7: A 2.4,0; K -2.4,0
SOT23 = smd 1 x 1.4: 1 -0.95,-1.1; 2 0.95,-1.1; 3 0,1.1
SO08 = smd 0.6 x 2.2: 1 -1.905,-2.6; 2 -0.635,-2.6; 3 0.635,-2.6; 4 1.905,-2.6; 5 1.905,2.6; 6 0.635,2.6; 7 -0.635,2.6; 8 -1.905,2.6
R0805 = smd 1.1 x 1.5: 1 -1.1,0; 2 1.1,0
R1005 = smd 0.7 x 0.9: 1 -0.65,0; 2 0.65,0
SOT23HV = smd 1 x 1.4: 1 -1.15,-1.7; 2 1.15,-1.7; 3 0,1.6
TO92-2MIL = drill 0.6 pad 0.813 long: 1 -2.54,0; 2 0,0; 3 2.54,0
1X1MM0 = drill 1 pad 1.676 octagon: 1 0,0
1X17 = drill 1.016 long: 1 -20.32,0; 2 -17.78,0; 3 -15.24,0; 4 -12.7,0; 5 -10.16,0; 6 -7.62,0; 7 -5.08,0; 8 -2.54,0; 9 0,0; 10 2.54,0; 11 5.08,0; 12 7.62,0; 13 10.16,0; 14 12.7,0; 15 15.24,0; 16 17.78,0; 17 20.32,0
1X10 = drill 1.016 long: 1 -11.43,0; 2 -8.89,0; 3 -6.35,0; 4 -3.81,0; 5 -1.27,0; 6 1.27,0; 7 3.81,0; 8 6.35,0; 9 8.89,0; 10 11.43,0
0204/13 = drill 0.813 octagon: 1 -6.872,0; 2 6.872,0
RING = drill 3 pad 4 round: 1 -3.15,0; 2 3.15,0
1X01 = drill 1 pad 1.676 octagon: 1 0,0
1X02 = drill 1.016 pad 1.676 long: 1 -1.27,0; 2 1.27,0
TO247BH = drill 1.499 long: D 0,-10.16; G -5.588,-10.16; S 5.588,-10.16 | hole 4.115: 0,9.144
SOT23-BEC = smd 1 x 1.4: B -0.95,-1.1; C 0,1.1; E 0.95,-1.1
R2512 = smd 1.8 x 3.4: 1 -3.1,0; 2 3.1,0
0207/10 = drill 0.813 octagon: 1 -5.08,0; 2 5.08,0
R1206 = smd 1.3 x 1.7: 1 -1.55,0; 2 1.55,0
B64Y = drill 0.813 long: A 2.54,0; E -2.54,0; S 0,0
0204V = drill 0.813 octagon: 1 -1.27,0; 2 1.27,0
WIRE = drill 0.813 octagon: 1 -8.25,0; 2 8.25,0
SOT23' = smd 1 x 1.4: B -0.95,-1.1; C 0,1.1; E 0.95,-1.1
EE14 = drill 0.6 pad 1 long: 1 4.25,-5; 2 4.25,5; 3 -4.25,5 | drill 0.6 pad 1.016 long: 4 -4.25,2.5; 5 -4.25,-2.5; 6 -4.25,-5
SO8-5 = smd 0.61 x 1.626: 1 -1.27,-2.54; 2 0,-2.54; 3 1.27,-2.54; 4 2.54,-2.54; 5 3.175,3.81; 6 1.27,3.81; 7 0,3.81; 8 -1.27,3.81
SO16DW = smd 0.6 x 2.2: 1 -4.445,-4.6; 2 -3.175,-4.6; 3 -1.905,-4.6; 4 -0.635,-4.6; 5 0.635,-4.6; 6 1.905,-4.6; 7 3.175,-4.6; 8 4.445,-4.6; 9 4.445,4.6; 10 3.175,4.6; 11 1.905,4.6; 12 0.635,4.6; 13 -0.635,4.6; 14 -1.905,4.6; 15 -3.175,4.6; 16 -4.445,4.6
SOT223 = smd 1 x 2: 1 -2.3,-3.15 | smd 1.5 x 2: 2 0,-3.15; 3 2.3,-3.15 | smd 3.8 x 2: 4 0,3.15

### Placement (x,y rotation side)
1HIDRV  34,98 45 top
1LODRV  33,70 90 top
2HIDRV  33.75,27.75 135 top
2LODRV  33,44 90 top
BLACK2  9,92 180 bottom
C1  88,109 0 bottom
C2  40,17 90 top
C3  70,109 180 bottom
C4  51,109 180 bottom
C5  not placed on the board
C6  53.5,23 270 top
C7  90,79 0 top
C8  53.5,18 0 top
C9  93,95.5 0 top
C10  45.3,7.8 0 top
C11  34,98 45 top
C12  33.75,27.75 135 top
C13  52,29 270 top
C14  55,95 0 top
C15  40,70 90 top
C16  41,44 90 top
C17  30,54 270 top
C18  10,64 90 bottom
C19  20,57 180 top
C20  18,110 180 bottom
C21  39.99,92.01 45 top
C22  39,33 135 top
C23  52,-13 90 top  (outside the outline)
C24  63,-12 270 top  (outside the outline)
CY1  80,51 0 bottom
CY4  80.1,35.3 0 bottom
D1  25.86,31.28 180 top
D2  90,32 90 top
D3  75,81.7 270 top
D4  90,48 90 top
D4SN  80,26.6 180 bottom
D4SN1  80,43 180 bottom
D5  29.5,35 0 top
D6  45,98 180 top
D7  50,100 90 top
D8  44.93,32.07 0 top
D9  80,80 90 top
D10  35,85 270 top
D13  17.5,44.5 90 top
D14  17.5,72 90 top
D15  25,44 0 top
D16  25,71 0 top
D17  24,21 0 top
D18  23.5,101 0 top
D19  30,59 180 top
D20  50,63 90 top
D21  50,59 90 top
D22  52,-19 270 top  (outside the outline)
D23  63,-17.9 270 top  (outside the outline)
FUSE  39,56 270 top
HOT1  74.4,10.1 180 top
HOT2  66.8,10.1 180 top
HOT3  61.8,10.1 180 top
HOT4  54.4,10 0 top
HVL  66,69 90 top
HVL1  59,27 90 top
HVT1  86.3,89.6 180 top
IC3  47.8,16.1 0 top
JDRAIN  94,30 270 top
JDRN1  94,45 0 top
JP1  58,-7 0 bottom  (outside the outline)
JP2  58,-27 180 bottom  (outside the outline)
JP7  58,13 0 bottom
JSORC1  94,52 0 top
JSOURCE  94,35.6 270 top
L1  62,139 90 bottom  (outside the outline)
L2  62,139 270 bottom  (outside the outline)
MAS1  75,75 270 top
MAS2  75,72 90 top
MINUS  60,107 270 bottom
NTC  39.9,5.9 180 bottom
P+1  91,75 270 top
P+2  91,72 90 bottom
PLUS  78,114 270 bottom
Q1  0,46.5 90 top
Q2  0,77.5 90 top
Q3  0,16 90 top
Q4  0,109.5 90 top
Q5  30.5,11 180 top
Q6  2,77.5 90 top
Q7  2,46.5 90 top
Q8  2,16 90 top
Q9  2,109.5 90 top
Q10  35,63.75 90 top
R1  22,39.25 180 top
R2  34,13 180 top
R3  82.3,95.5 270 top
R4  83,90 90 top
R4SN  79.8,30 0 bottom
R4SN1  80,46 0 bottom
R5  22,17 0 top
R6  91.6,90.2 0 top
R7  20.5,72 270 top
R8  85,81 270 top
R9  92.5,8 0 top
R10  87.2,17.5 270 top
R11  94.3,86.9 90 top
R12  88,11 270 bottom
R13  82.9,78.9 270 top
R14  79.3,90.1 180 top
R15  22,97 0 top
R16  22.1,67 180 top
R19  36.1,60.2 270 top
R20  30,63 0 top
R21  40,61.5 0 top
R22  43.3,50.6 180 top
R23  33,59 90 top
R24  33,54 90 top
R25  41,22 270 top
R26  43,22 270 top
R27  97,9.4 90 top
R28  92,12.7 270 top
R29  90,17.5 270 top
R30  19,101.5 270 top
R31  19,22 270 top
R32  20.5,44.5 270 top
R33  33,70 180 top
R34  34,98 135 top
R35  33,44 180 top
R36  33.75,27.75 225 top
R37  39,-13 90 bottom  (outside the outline)
R38  60.4,-10.8 270 top  (outside the outline)
R39  55.5,-10.8 270 top  (outside the outline)
R40  73.3,-10.8 270 top  (outside the outline)
R41  65.6,-10.8 270 top  (outside the outline)
RED1  not placed on the board
ROUT5  22,50 180 top
ROUT6  22,27 180 top
ROUT7  22,77 0 top
ROUT8  22,106 180 top
RSENS  34,113 180 bottom
T3  BC848  [SOT23']  74.4,93.8 0 top
TRAFO  85,90 90 bottom
U$1  56.7,-18.5 0 top  (outside the outline)
U$2  66.7,-18.5 0 top  (outside the outline)
U$3  50,86 225 top
U$4  51.5,41 270 top
V12_1  83,75 270 top
V12_2  83,72 90 top
VENT  28,6 0 bottom
VREG  47.5,23 0 top

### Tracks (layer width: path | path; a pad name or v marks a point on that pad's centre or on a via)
1HO  (via drill 0.6 pad 1.5)
  Top 0.5: D20.1 52.95,62.05 v53,62 | 64,77 58,77 54.9,80.1 54,81.1 U$3.12
  Top 0.6: 65.6,16.4 64,18 v64,62 64,77
  Top 1: 65.6,14.4 JP7.6 65.7,12.92 HOT2.2
  Top 1.5: 65.6,14.4 65.6,16.4
  Bottom 0.5: v64,62 v53,62
1LO  (via drill 0.6 pad 1.5)
  Top 0.5: 73,16 68,21 | 68,78 66,81 59,81 56.9,82.1 56.2,82.5 U$3.14
  Top 0.6: 68,21 v68,58 68,78
  Top 1: 73,16 73.24,15.76 JP7.3 73.3,12.94 HOT1.2 | D21.1 52,58.05 v53,58
  Bottom 0.5: v68,58 v53,58
1LO2HO  (via drill 0.6)
  Top 0.5: U$2.3 68,-23.7 67,-24.7 67,-25 | 67,-25 67,-25.89 JP2.9 | v58,-23.4 56.83,-22.33 56.73,-22.23 U$1.2 | v66.9,-25 67,-25
  Bottom 0.5: v58,-23.4 64.6,-23.3 66,-24 v66.9,-25
2HO
  Top 0.5: 57,29 57,32 60,34 60,40 58.63,40.37 U$4.12
  Top 0.6: 55.5,14.8 57.5,17 57.5,21 57,22 57,29
  Top 1: HOT4.2 55.5,12.96 JP7.10
  Top 1.5: JP7.10 55.5,14.8
2LO
  Top 0.5: 60.54,14.54 61,16 61,43 60.91,42.91 U$4.14
  Top 1: HOT3.2 60.7,12.84 JP7.8
  Top 1.5: JP7.8 60.54,14.54
6YU
  Top 0.5: R34.1 | U$3.8 42.5,87.2 42.5,89.5 R34.1 | R34.1 35.1,96.01 1HIDRV.2 1HIDRV.3
12V  (via drill 0.6)
  Top 0.5: 49.11,-10.89 49.32,-10.06 JP1.12 | 49.11,-21 49.51,-21.4 | U$2.1 64.04,-20.84 D23.A 63.7,-20.3 v64.5,-20 | v49.11,-20 v49.1,-20 | D22.A 52.6,-21.4 53,-21 55.39,-21 U$1.1
  Top 1: JP2.2 49.11,-21 v49.11,-20 49.11,-10.89 | 49.51,-21.4 D22.A
  Bottom 0.5: v49.1,-20 v64.5,-20
A
  Top 1: D9.A TRAFO.6
ACL  (1 unrouted)
  Top 1.5: R27.2 97,14
  pour Top: 66,138 66,129 24,129 24,139 25,140 48,140 51,137
ASG
  Top 0.5: 68,-10.8 U$2.6 | 68,-10.8 68,-7.16 JP1.5 | C24.1 63.45,-10.45 64,-10.8 68,-10.8
B1C2
  Top 0.406: R6.1 88.05,91.7 HVT1.1 87.45,95.55 86,97 82.9,97 | 82.7,97 R3.1 82.9,97 | T3.C 75.6,96.6 76,97 82.7,97 | 82.9,97 82.7,97
  pour Top (isolate 2): 88,92 88,97 73,97 73,94 86,94 86,92 89,89 91,89 91,91
BLACK  (via drill 0.6, 0.6 pad 1.5)  (2 unrouted)
  Top 0.5: v6,76 7,76 7,78 11,78 | v14,95 13,95
  Top 1: 18,114 18,106.1 ROUT8.2 18.9,103.15 R30.1
  Top 3: 15,115.09 16.91,115.09 18,114 | 15,115.09 Q9.S Q4.S | v14,95 BLACK2.1 7,92 | v14,119 15,115.09
  Route2 0.5: v6,76 45,72 46,73 61,73 63,71 v66,71 | v14,119 16,119 18,117 18,99 v14,95
  other vias: 5,69
  pour Top (isolate 2): 16,95 9,88 6,88 6,79 13,79 13,76 8,76 6,74 6,70 7,67.5 12,67.5 12,66 3,66 3,96 11,96
  pour Bottom (isolate 2, rank 5): 17,95 10,88 7,88 7,79 14,79 14,76 9,76 7,74 7,70 8,67.5 13,67.5 13,66 4,66 4,96 12,96
BT1
  Top 0.406: T3.B 73,90.75 73,86.2 74.8,85.2 D3.C 75.4,85 76.9,86.3 77.2,86.7 78,88.3 77.8,88.8 R14.2
  pour Top (isolate 1.5, rank 2): 80,90 80,88 76,84 73,84 73,93 75,93 75,92 77,90
C1
  Top 0.406: HVT1.3 86.3,87.7 87,87
  Top 1: 87,87 87,86.25 TRAFO.4
COM1
  Top 0.5: ROUT5.1 26,50 30,46 29.77,46 2LODRV.5 35.91,45.91 36,46 36.23,46 2LODRV.4 40.64,45.91 C16.2 43.55,45.55 45,47 49,47 50,46 50,44 49.83,44.17 U$4.2
COM2
  Top 0.5: 31,73 30.4,72.4 30.4,72.6 30,73 29.67,72.67 1LODRV.5 | 35,73 36,72 35.69,72 | 40.45,71.55 C15.2 41,72.55 41,76 51,86 51,89.4 49.4,91.1 U$3.2 | 26,77 25.81,77.19 ROUT7.2 | 1LODRV.4 36.33,72.67 36,73
  Top 1: 31,73 35,73 36,73 39,73 40.45,71.55
  Top 1.5: 30,73 26,77
DFG
  Top 0.3: JP7.9 58,15
  Top 0.5: HVL1.1 59,22 59.25,21 59.25,17 58,15
DFTY
  Top 0.5: U$2.8 65.05,-14.6 D23.K C24.2
DIS
  Top 0.5: R19.2 36.5,58.8 FUSE.1
DR2
  pour Top (isolate 2, rank 2): 95,48 81,48 81,41 95,41
  pour Bottom (isolate 2, rank 2): 95,48 81,48 81,41 95,41
DRAIN
  pour Top (isolate 2, rank 2): 95,32 81,32 81,25 95,25
  pour Bottom (isolate 2, rank 2): 95,32 81,32 81,25 95,25
EB
  Top 0.406: R14.1 81.3,91.1 R4.2 | 84.95,91.1 HVT1.2
  Top 1: R4.2 84.95,91.1
ET
  Top 0.5: 35.6,70 36,70 | 36,70 43,70 43,76 53,86 53,90 50.6,92.4 U$3.1 | 1LODRV.3 36.33,70.33 36,70 | 1LODRV.2 36.33,69.67 36,70
  Top 1: R33.1 35.6,70
GAT1
  Top 1: R32.2 22.25,42.95 D15.C
  pour Top (isolate 2): 9,42 17,42 17,44 24,44 22,38 9,38
GAT1RD
  Top 0.5: R1.1 25.81,41.81 | 2LODRV.6 29.67,44.09 29.77,44 29.77,43.46 2LODRV.7
  Top 1: 28,44 D15.A | 29.77,44 R35.2
  Top 1.5: 29.77,44 28,44 25.81,41.81
GAT2
  Top 0.5: D14.C 12.3,70.3 12,70 12,72 12.07,72 Q6.G
  Top 1: R7.2 22.85,70.45 D16.C
  pour Top (isolate 2, rank 2): 8,73 14,73 21,71 24,71 24,68 15,68 13,70 8,70
GAT2RD
  Top 0.5: R33.2 30.31,70 1LODRV.7 | 1LODRV.6 29.67,70.33 30,70
  Top 1: 26.7,70 26.7,68.7 26,68 26,67.8 R16.1 | 26.7,70 D16.A | 26.7,70 30,70 R33.2
GAT3
  pour Top (isolate 2, rank 3): 9,12 9,9 14,9 23,11 23,22 18,20 18,12
GAT3RD
  Top 0.5: 30.95,24.95 2HIDRV.6 | 2HIDRV.7 31.05,24.95 31,25
  Top 1: 28,22 30.95,24.95 31,25 R36.2
  pour Top (isolate 1.5, rank 2): 28,25 35,28 32,23 29,23 28,22 26,17 25,17 25,22 26,22
GAT4
  Top 0.5: Q4.G 12.07,102 14,102 17,101 17.39,100.18
  Top 1: 17.62,99.95 R30.2 20.75,99.95 D18.C | 17.39,100.18 17.62,99.95 | R15.1 18.9,98.9 19,99 18.57,99 17.62,99.95
  pour Top (isolate 1.5): 8.9,104.5 12.9,104.5 15,103 18,103 19,102 19,101 18,100 15,100 14,101 12,101 11,102 9,102
GAT4RD
  Top 0.5: 1HIDRV.7 31.64,100.36 1HIDRV.6
  Top 1: 27,101 28,102 30,102 31.64,100.36 R34.2 | 27,101 D18.A | R15.2 25.1,99.1 27,101 | R34.2
GND
  Top 0.5: U$1.4 59.54,-22.24 59.6,-23 60,-25 59,-25 59,-26.73 JP2.6 | JP1.11 53,-7.08
  pour Top (isolate 1): 33,-1 83,-1 83,-31 33,-31
  pour Bottom (isolate 1): 33,-1 83,-1 83,-19 33,-19
IFB  (1 unrouted)
  Top 0.5: ROUT5.2 20,51.1 | R20.1 24,63 23,62 22,62 21,61 19.07,61 17.07,59 17.07,57.39 C19.2
  Top 1: D14.A 20.35,73.7 R7.1 | JP2.10 78,-24 78,-7.32 JP1.1
  Bottom 0.406: Q1.S 17.07,59 19,59 | 19,84 18.08,83.08 16,82.55 14.99,83.09 Q2.S
  pour Bottom (isolate 2): 28,113 28,109 24,109 21,106 21,88 20,87 20,59 14,52 10,51 9,52 9,55 15,62 15,81 9,81 8,82 8,85 10,85 18,93 18,107 24,113
  pour Top (isolate 2, rank 2): 20,121 29,121 29,109 20,109
  pour Top (isolate 2, rank 2): 9,51 9,54 10,54 12,56 17,62 23,62 21,60 20,60 19,59 19,54 22,51 22,46 15,46 15,51
  pour Top (isolate 2, rank 2): 8,85 19,85 19,74 14,74 14,81 8,81
JDH  (1 unrouted)
  Top 0.3: 66,68 66,19 68,17 68,13.16 JP7.5
LIN
  Top 0.5: 61.81,-23.3 61.91,-23.11 60.8,-22 60.8,-18.7 58,-18.7 U$1.3 | 61.81,-23.3 JP2.7 | U$2.2 66.73,-22.27 66,-23.3 61.81,-23.3
MASS  (via drill 0.6 pad 1.5)
  Top 0.254: 42,110 42,112 | C4.- 53,109 | 42,108 42,110 | 42,110 RSENS.2
  Top 0.406: C7.- 91.55,81.45 88.7,82.4 85.8,82.4 R8.1 84.9,82.1 v83.6,83.3 | C9.2 94.1,95.1 v95.4,93.8 | TRAFO.5 82.5,86.5 83,87 R4.1
  Top 0.5: C4.- 59,109 60,108 60,98 | D5.A 34,37.4 | U$3.15 56.41,83.99 58.5,83.2 | FUSE.4 36.4,52.4 36,52 | U$4.15 58.18,44.17 59,45 59,49 v60,50
  Top 1: v75.7,90.2 75.7,92.35 T3.E | 34,37.4 v34,38
  Top 1.5: v55.3,19.9 54.9,21.1 | C8.- 55.3,19.7 55,20
  Bottom 0.406: v75.7,90.2 76,76 MAS1.1 | v95.4,93.8 95.4,92.4 95,92 | 83,83 v83.6,83.3
  Bottom 0.5: 60,102 MINUS.1
  Bottom 1: 50,97 56,103 | 60,99 60,102
  Bottom 1.5: v34,38 36,40 36,66
  other vias: 56,64 51,71 46,75
  pour Bottom (isolate 2): 96,97 96,73 73,73 73,97
  pour Top (isolate 2, rank 5): 96,97 96,73 73,73 73,97
  pour Bottom (isolate 1, rank 4): 40,80 60,100 99,100 99,22 89,12 89,4 29,4 29,14 44,28 46,30 46,38 40,38
  pour Top (isolate 1, rank 4): 51,93 57,100 100,100 98,23 88,4 26,4 26,10 51.5,36 51.5,48 33,48 29,53 29,85 43,84
  pour Bottom (isolate 2, rank 2): 40,113 44,113 44,108 45,107 54,107 54,110 62,110 62,107 71,107 71,110 86,110 87,109 87,101 40,101
  pour Top (isolate 2, rank 2): 32,121 44,121 44,108 45,107 54,107 54,110 62,110 62,107 71,107 71,110 86,110 87,109 87,101 41,101 32,110
  pour Bottom (isolate 1.5): 48,99 52,97 36,82 35,80 33,82 32,81 32,78 39,71 39,64 37,64 35,65 35,72 30,77 30,82 34,86
N$1
  Top 0.406: VENT.1 29.27,6.97 | 29.3,7.5 30,9.8 Q5.3
  Top 1.5: 29.27,6.97 29.3,7.5
N$2
  Top 0.406: Q5.1 R2.2
N$3
  Top 0.4: R2.1 JP7.17
N$6
  Top 0.406: 81.95,94.25 R3.2
  Top 1: TRAFO.1 81.95,94.25
N$7
  Top 0.406: 91.15,94.3 C9.1
  Top 1: TRAFO.2 91.15,94.3
N$8
  Top 0.406: R11.2 94.2,90.15 R6.2
N$9  (via drill 0.6)
  Top 0.5: R21.1 38.9,59.1 v39,59 39,57 38.64,56.63 FUSE.2 | FUSE.5 41.5,54 40,54 v39,53 39.4,52.6 R22.2
  Bottom 0.5: v39,53 v39,59
N$10
  Top 0.406: R8.2 84.8,80.1 R13.1 D3.A
N$12
  Top 0.5: U$4.8 43.56,36.55 43,37 36,30 | 35.66,29.66 36,30 | 2HIDRV.3 35.66,30.34 36,30 | 35.66,29.66 2HIDRV.2 | R36.1 35.66,29.66
N$14
  Top 0.5: R20.2 31.1,60.25 D19.1
N$15
  Top 1: R40.1 73.3,-7.06 JP1.3
N$16
  Top 0.5: 2LODRV.2 36.33,43.67 36,44 36,44.2 36.33,44.53 2LODRV.3 | 38,44 38.26,43.74 39.74,43.74 40,44 44,44 45.44,45.45 U$4.1
  Top 0.6: 38,44 36,44 36,44.2 35.9,43.97
  Top 1: R35.1 36,44
N$17
  Top 0.406: R26.2 R25.2
  Top 0.5: VREG.1 45.2,20 44.4,20.8 43.1,20.8 R26.2
N$18
  Top 0.5: Q10.E 36.8,64.25 47.6,64.25 D20.3 D21.3
N$19
  Top 0.5: U$2.7 66.73,-13.1 R41.2
N$20
  Top 0.5: D1.C 27.1,32.7
  Top 1: 27.1,32.7 D5.K
N$21
  Top 1: R38.1 60.5,-7.04 JP1.8
N$22
  Top 0.5: 69,-19 69,-17
N$23
  Top 0.5: R27.1 94.2,7.85 R9.2
N$24
  Top 0.5: D6.C 46.6,97.9 D7.K
N$25
  Top 0.5: Q10.B 35.95,62.05 R19.1
N$26
  Top 0.5: R23.2 33,61.9 Q10.C
N$27
  Top 1: R39.1 55.5,-7.04 JP1.10
N$29
  Top 0.5: R28.1 92,15 91,16 90.4,16 R29.2 R10.2 88,15.6 R12.E
N$30
  Top 0.5: R12.A 90.49,8.46 R9.1 91,8.05 91,10 92,11 R28.2
N$32
  Top 0.5: U$1.5 60.01,-14.49 60,-14 60,-12.47 R38.2
N$33
  Top 0.5: U$1.7 56.73,-13.1 R39.2
N$34
  Top 1: R41.1 65.6,-7.02 JP1.6
N$35
  Top 0.5: U$2.5 72.38,-14.69 R40.2
O_IFB  (via drill 0.6)
  Top 0.5: C17.1 D19.3 R23.1 R24.2 33.27,55.37 FUSE.3 FUSE.6 44.64,55.37 v47,53 | v78,16 78,13.32 JP7.1
  Bottom 0.5: v47,53 69,53 69,26 v78,16
PUMP+
  Top 0.254: P+2.1 91,73 91.38,73.27
  Top 0.406: P+1.1 94,75 95,76 95,83 94.65,84.35 R11.1 90.4,85.35 TRAFO.3
  Bottom 0.5: C1.+ 96,109 97,108 97,102 98,101 98,74 96,72 P+2.1
  pour Top (isolate 2, rank 2): 95,86 95,73 91,73 91,77 94,77 94,84.6 90,84.6 90,86
  pour Bottom (isolate 2, rank 3): -16,24 -16,8 7,8 7,14 24,14 27,16 27,103 40,103 40,113 44,113 45,112 45,109 50,109 50,112 64,112 64,108 65,107 70,107 70,112 86,112 89,109 89,107 98,107 98,121 16,121 13,111 6,111 6,118 -17,118 -17,102 5,102 5,107 14,107 19,112 29,112 29,108 22,108 20,105 20,21 18,19 6,19 6,24
  pour Top (isolate 2, rank 4): 3,24 3,8 7,8 7,14 24,14 26,16 27,103 39,103 39,113 44,113 45,112 45,109 50,109 50,112 64,112 64,108 65,107 70,107 70,112 86,112 89,109 89,107 99,107 99,121 32,121 32,111 6,111 6,118 1,118 1,102 6,102 6,108 23,108 23,21 18,17 6,17 6,24
RED  (via drill 0.6 pad 1.5)  (3 unrouted)
  Top 0.5: HVL1.2 58.9,29.15 59,29.5
  Route2 0.5: L2.1 L1.2
  other vias: 17,31.5 59,30.5
  pour Bottom (isolate 2, rank 4): 2,48 13,48 13,45 8,45 6,43 6,34 18,34 18,24 11,20 10,20 9,21 2,27
  pour Top (isolate 2): 10,23 11,35 18,35 18,24 19,24 17,22 15,22 14,21 10,21
  pour Top (isolate 2, rank 3): 1,63 13,63 13,60 7,60 7,48 13,48 13,45 8,45 6,43 6,35 12,35 12,21 11,20 10,20 9,21 9,27 1,27
SCR2
  pour Top (isolate 2): 95,53 95,50 81,50 81,53
  pour Bottom (isolate 2): 95,53 95,50 81,50 81,53
SD  (via drill 0.6)
  Top 0.5: U$4.13 54.37,41.63 54,42 54,55 | FUSE.7 46.64,56.63 48.27,55 54,55 | 54,55 59,55 v58,71 | U$3.13 54.8,82.2 56.6,80.4 58.3,79.6 v59,79
  Bottom 0.5: v58,71 v59,79
SERT
  Top 0.5: 58,-10.9 U$1.6 | 58,-10.9 JP1.9 | C23.2 52.85,-11.45 53.8,-10.8 57.6,-10.8 58,-10.9
SNUB1
  pour Top (isolate 2, rank 2): 79,53 79,41 72,41 72,53
  pour Bottom (isolate 2, rank 2): 79,53 79,41 72,41 72,53
SNUB2
  pour Top (isolate 2, rank 2): 79,37 79,25 72,25 72,37
  pour Bottom (isolate 2, rank 2): 79,37 79,25 72,25 72,37
SOURCE
  pour Top (isolate 2): 95,37 95,34 81,34 81,37
  pour Bottom (isolate 2): 95,37 95,34 81,34 81,37
TFB  (via drill 0.6)  (1 unrouted)
  Top 0.4: C2.1 40,13.22 JP7.16
  Top 0.5: NTC.1 38.63,7.63 v39,8 | v40,11 40,12.78 JP7.16
  Top 1: JP1.16 40.22,-9.78 40,-10 39,-10 | 39,-10 37,-10 37,-7.68 JP1.17 | R37.2 39,-10
  Bottom 0.5: v39,8 39,10 v40,11
V12  (via drill 0.6, 0.6 pad 1.27, 0.6 pad 1.5)  (1 unrouted)
  Top 0.254: V12_2.1 82,72 82,73 82.17,73
  Top 0.406: C7.+ 88.45,77.45 87,76 84,76 V12_1.1 | V12_1.1 R13.2 | D9.K 80,78 V12_1.1 | JP7.12 50.2,13.18 | VENT.2 26.73,6.27
  Top 0.5: 31,67 30.4,67.6 30.17,67.6 1LODRV.8 | 34.75,67.25 34.5,67 | 50.3,12.92 JP7.12 | v35,79 34.55,81 | 2LODRV.8 29.67,41.33 30,41 | 2LODRV.1 36.33,41.67 37,41 | 1LODRV.1 36.33,67.33 36,67 | D10.A 35.14,82.46 | U$4.3 44.91,42.91 v44,43 41.55,42.45 C16.1 | 49.4,31.5 49.9,31.5 50.85,30.55 C13.1 | R21.2 41.1,60.6 v42,59.7 | U$3.3 48.09,90.91 v46,93 48,95 C14.1
  Top 0.6: 41.69,58.7 FUSE.8 | 49.4,31.5 D8.A
  Top 1: 29.69,41 30,41 37,41 41,41 C16.1 | v42,59.7 41.69,58.7 | v72,67 83,67 V12_2.1 | 34.5,67 31,67 | 34.75,67.25 35,67 36,67 v42,67 41,68 C15.1 | v50.3,10.5 50.3,12.92 | 50.34,13.04 IC3.3 50.3,16.14 50.3,16.8 50,17.1 50,18 | VREG.3 49.8,18.2 50,18 | C8.+ 50.1,17.9 50,18
  Top 1.5: v49.8,31.6 49.9,31.5 50.3,31.1 | JP7.12 50.34,13.04 | 26.73,6.27 v26.7,8.7
  Bottom 0.406: v26.7,8.7 27,9 | v49.8,31.6 50.4,31
  Bottom 0.5: 50,17 50.1,17 50.3,16.8 | 50,30.5 49.68,30.6 50,30.6 v49.8,31.6 | 42,49 42,52 | v46,93 47,90 35.5,78.5
  Bottom 1: 27,9 30,13 32,16 48.3,32.3
  Bottom 1.5: v42,67 v42,59.7 42,49 42,42 v44,43 42,40 42,38.6 48.3,32.3 50,30.6 | v35,79 35.5,78.5 42,72 v42,67 | v42,67 v72,67 | 50.3,16.8 v50.3,10.5 | 50,30.5 50,17
  pour Top (isolate 2): 89,79 89,73 80,73 80,78 87,78
VB1
  Top 0.5: 1HIDRV.1 34.3,94.3 33,93 32,93 29,96 29,97.71 1HIDRV.8 | 36.8,91.8 C21.1 39.4,87.6 43,83 44,83 46,85 45.8,85.2 45.8,85.7 44.5,87 U$3.7
  pour Top (isolate 1.5, rank 2): 29,99 47,85 44,82 34,88 26,96
VB2
  Top 0.5: 39.18,29 40,29 41,30 | 41,30 42,31 41.99,31.01 | 41,30 42.4,31 D8.K 43.5,33.5 45,35 50,35 50,38 49,38 48.83,37.83 U$4.7 | 2HIDRV.1 37.45,28.55 38,28 | 2HIDRV.8 32.95,24.05 34,23
  pour Top (isolate 1.5): 33,23 34,22 43,31 43,33 42,33 33,24
VBH
  Top 0.5: U$1.8 52.14,-14.69 C23.1 D22.K
VDD  (via drill 0.6, 0.6 pad 1.5)  (1 unrouted)
  Top 0.5: IC3.1 45.26,17.56 45.5,17.8 46.4,17.8 46.7,18.1 | VREG.4 47.5,23.5 47.9,23.1 | JP7.14 45.3,11.3 v45.4,10.7 | v41,8 41,6.07 NTC.2 | C6.+ 52.5,24.5 v52,24 | v57,34 59,36 59,38 57.91,39.09 U$4.11 | U$3.11 51.91,81.29 53.3,79.9 53.3,78.4 56.2,75.3 56.7,75 62,75 v62,48
  Top 1: R26.1 47.9,23.1 48,23 48,21.6 47.6,21.2 47.6,19 46.7,18.1
  Top 1.5: JP7.14 45.3,16.06 IC3.1
  Bottom 0.5: v45.4,10.7 45,10 v41,8 | v52,24 52,25 54,27 54,31 v57,34 62,39 v62,48
  pour Top (isolate 0.8): 45,25 53,25 53,24 51,20 49,20 49,19 46,15 43,15 43,23
VFB  (via drill 0.6)  (1 unrouted)
  Top 0.4: C10.1 44.2,5.2 49,5
  Top 0.5: R12.S 86,11 82,5 49,5 | JP7.15 42.76,9.84 C10.1 | v55,-23.8 55.3,-24.23 JP2.5
  Top 1: v42.76,-22.76 JP1.15
  Bottom 0.5: v42.76,-22.76 51.76,-22.76 v55,-23.8
VS3
  Top 0.5: ROUT6.1 25.25,28.1 | 25.25,28.1 25.3,28.51 | 2HIDRV.4 34.55,31.45 34,32 | U$4.6 42.09,39.09 39,36 38.81,35 C22.2 | 2HIDRV.5 30.05,26.95 29,28 | 29,28 29.9,28 C12.2 | 29,28 25.35,28 25.25,28.1
  pour Top (isolate 1.5): 24,32 26,32 29,29 30,29 36,35 42,35 42,34 38,34 31,27 28,26 24,29
VS4
  Top 0.5: 1HIDRV.5 32.99,101.99 34,103 34,102.1 C11.2 36.05,99.95 38,98 38,97 | C21.2 41.29,93.01 | U$3.6 45,88.31 44.6,88.7 44.6,88.8 43.9,89.5 43.9,91.1 42,93 41.2,93 C21.2 | 1HIDRV.4 37.99,96.99 38,97 | 38,97 39,98 42,95 41.09,94.09 C21.2
  pour Top (isolate 1.5): 26,107 30,107 39,98 44,98 44,93.5 41,90.5 40,95 34,101 33,101 29,105 26,105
